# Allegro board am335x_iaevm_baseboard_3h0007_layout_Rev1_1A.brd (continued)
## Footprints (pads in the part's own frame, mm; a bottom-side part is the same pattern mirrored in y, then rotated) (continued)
HEADER_2X1
  rect 1.778x1.778 hole 1.016: 1(0,0)
  round 1.778 hole 1.016: 2(0,2.54)
HEADER_5X1
  rect 1.778x1.778 hole 1.016: 1(0,0)
  round 1.778 hole 1.016: 2(2.54,0) 3(5.08,0) 4(7.62,0) 5(10.16,0)
HEADER_10X2_TH
  oval 0.914x1.168 hole 0.66: 1(0,0) 2(0,1.27) 3(1.27,0) 4(1.27,1.27) 5(2.54,0) 6(2.54,1.27) 7(3.81,0) 8(3.81,1.27) 9(5.08,0) 10(5.08,1.27) 11(6.35,0) 12(6.35,1.27) 13(7.62,0) 14(7.62,1.27) 15(8.89,0) 16(8.89,1.27) 17(10.16,0) 18(10.16,1.27) 19(11.43,0) 20(11.43,1.27)
JUMP2X14-6040-1
  round 1.397 hole 1.016: 1(0,0) 2(0,2.54) 3(-2.54,0) 4(-2.54,2.54) 5(-5.08,0) 6(-5.08,2.54) 7(-7.62,0) 8(-7.62,2.54) 9(-10.16,0) 10(-10.16,2.54) 11(-12.7,0) 12(-12.7,2.54) 13(-15.24,0) 14(-15.24,2.54) 15(-17.78,0) 16(-17.78,2.54) 17(-20.32,0) 18(-20.32,2.54) 19(-22.86,0) 20(-22.86,2.54) 21(-25.4,0) 22(-25.4,2.54) 23(-27.94,0) 24(-27.94,2.54) 25(-30.48,0) 26(-30.48,2.54) 27(-33.02,0) 28(-33.02,2.54)
JUMP2X20-6040-1
  round 1.524 hole 1.016: 1(0,0) 2(0,2.54) 3(-2.54,0) 4(-2.54,2.54) 5(-5.08,0) 6(-5.08,2.54) 7(-7.62,0) 8(-7.62,2.54) 9(-10.16,0) 10(-10.16,2.54) 11(-12.7,0) 12(-12.7,2.54) 13(-15.24,0) 14(-15.24,2.54) 15(-17.78,0) 16(-17.78,2.54) 17(-20.32,0) 18(-20.32,2.54) 19(-22.86,0) 20(-22.86,2.54) 21(-25.4,0) 22(-25.4,2.54) 23(-27.94,0) 24(-27.94,2.54) 25(-30.48,0) 26(-30.48,2.54) 27(-33.02,0) 28(-33.02,2.54) 29(-35.56,0) 30(-35.56,2.54) 31(-38.1,0) 32(-38.1,2.54) 33(-40.64,0) 34(-40.64,2.54) 35(-43.18,0) 36(-43.18,2.54) 37(-45.72,0) 38(-45.72,2.54) 39(-48.26,0) 40(-48.26,2.54)
MC-306
  rect 1.3x1.9 smd: 1(-2.75,-1.6) 2(2.75,-1.6) 3(2.75,1.6) 4(-2.75,1.6)
MHC-W21-601-LF
  round 1.524 hole 1.092: (-11.5,-3.05)
  round 2.108 hole 1.6: (9.5,-3.05)
  rect 0.6x2 smd: 1(6.875,0) 2(4.375,0) 3(1.875,0) 4(-0.625,0) 5(-3.125,0) 6(-5.625,0) 7(-8.05,0) 8(-9.75,0) 9(9.375,0)
  rect 1x1.5 smd: 10(5.65,-17) 11(3.15,-17) 12(-4.35,-17) 13(-6.85,-17)
  rect 0.7x2 smd: 14(-12.25,0) 15(-11.05,0)
  rect 0.5x2 smd: 16(-7.27,0) 17(-6.475,0) 18(-4.775,0) 19(-1.475,0) 20(0.225,0) 21(1.025,0) 22(2.725,0) 23(3.525,0) 24(-8.9,0) 25(-3.975,0) 26(-2.275,0)
  rect 1.3x2.4 smd: 27(-14.15,-17.05) 28(14.15,-17.05)
MS920SE-FL27E
  rect 2.286x0.762 smd: 1(0,1) 2(0,-1)
NORCOMP_DB9M_TH
  rect 1.6x1.6 hole 1.092: 1(0.051,0)
  round 1.6 hole 1.092: 2(-2.718,0) 3(-5.486,0) 4(-8.255,0) 5(-11.024,0) 6(-1.346,2.845) 7(-4.102,2.845) 8(-6.871,2.845) 9(-9.639,2.845)
  round 5.08 hole 3.048: 10(-17.983,1.422) 11(7.01,1.422)
RAPC712
  round 4.064 hole 3.556: 1(0,0)
  round 3.683 hole 3.048: 2(-2.997,-4.801) 3(-6.248,0)
SKT-TSOP48SM
  rect 1.524x0.305 smd: 1(-9.716,5.753) 2(-9.716,5.253) 3(-9.716,4.752) 4(-9.716,4.252) 5(-9.716,3.754) 6(-9.716,3.254) 7(-9.716,2.753) 8(-9.716,2.253) 9(-9.716,1.753) 10(-9.716,1.252) 11(-9.716,0.754) 12(-9.716,0.254) 13(-9.716,-0.246) 14(-9.716,-0.747) 15(-9.716,-1.247) 16(-9.716,-1.748) 17(-9.716,-2.248) 18(-9.716,-2.746) 19(-9.716,-3.246) 20(-9.716,-3.747) 21(-9.716,-4.247) 22(-9.716,-4.747) 23(-9.716,-5.248) 24(-9.716,-5.748) 25(9.716,-5.753) 26(9.716,-5.253) 27(9.716,-4.752) 28(9.716,-4.252) 29(9.716,-3.754) 30(9.716,-3.254) 31(9.716,-2.753) 32(9.716,-2.253) 33(9.716,-1.753) 34(9.716,-1.252) 35(9.716,-0.754) 36(9.716,-0.254) 37(9.716,0.246) 38(9.716,0.747) 39(9.716,1.247) 40(9.716,1.748) 41(9.716,2.248) 42(9.716,2.746) 43(9.716,3.246) 44(9.716,3.747) 45(9.716,4.247) 46(9.716,4.747) 47(9.716,5.248) 48(9.716,5.748)
SM-7351-CAP-0402
  round 0.635 smd: 1(-0.508,0) 2(0.508,0)
SM-7351-CAP-0603
  rect 1.092x1.041 smd: 1(-0.85,0) 2(0.85,0)
SM-7351-CAP-0805
  rect 1.346x1.524 smd: 1(-1,0) 2(1,0)
SM-7351-CAP-2917
  rect 2.413x2.54 smd: 1(3.175,0) 2(-3.175,0)
SM-7351-CAP-SMDCAN
  rect 4.15x1.65 smd: 1(3.05,0) 2(-3.05,0)
SM-7351-IND-0805
  rect 1.397x1.549 smd: 1(-0.95,0) 2(0.95,0)
SM-7351-RES-0402
  round 0.635 smd: 1(-0.508,0) 2(0.508,0)
SM-7351-RES-0603
  rect 1.143x1.092 smd: 1(-0.9,0) 2(0.9,0)
SM-7351-RES-0805
  rect 1.143x1.549 smd: 1(-1.1,0) 2(1.1,0)
SM_CRY_SCC18
  rect 1.4x2.2 smd: 1(-1.25,3.2) 2(-1.25,-3.2) 3(1.25,-3.2) 4(1.25,3.2)
SM_LED_0805
  rect 1.15x1.194 smd: 1(1.125,0) 2(-1.125,0)
SM_RES_0805_KELV
  rect 1.4x1.65 smd: 1(-1.3,0) 2(1.3,0)
  rect 0.127x0.127 smd: 3(-0.377,-1.186) 4(0.377,-1.186)
SM_RES_LVK12
  rect 1.75x1.1 smd: 1(-1.375,0.7) 2(1.375,0.7) 3(-1.375,-0.7) 4(1.375,-0.7)
SMCJ15CA
  rect 2.4x3.3 smd: 1(-3.3,0) 2(3.3,0)
SMD_SLF7055T
  rect 1.5x2.2 smd: 1(-3.15,0) 2(3.15,0)
SMDFUSEBLK
  rect 4.242x3.81 smd: 1(-3.175,0) 2(3.175,0)
SMDMSOP_10
  rect 0.254x1.016 smd: 1(-1,-2.5) 2(-0.5,-2.5) 3(0,-2.5) 4(0.5,-2.5) 5(1,-2.5) 6(1,2.5) 7(0.5,2.5) 8(0,2.5) 9(-0.5,2.5) 10(-1,2.5)
SMDSC70-5
  rect 0.406x1.016 smd: 1(-0.65,-0.95) 2(0,-0.95) 3(0.65,-0.95) 4(0.65,0.95) 5(-0.65,0.95)
SOIC_8
  rect 0.61x2.184 smd: 1(-1.905,-2.603)
  oval 0.61x2.184 smd: 2(-0.635,-2.603) 3(0.635,-2.603) 4(1.905,-2.603) 5(1.905,2.603) 6(0.635,2.603) 7(-0.635,2.603) 8(-1.905,2.603)
SOT23-3
  rect 0.787x0.889 smd: D(0,1.003) G(-0.94,-1.003) S(0.94,-1.003)
SW_B3SL-1022P
  rect 2.75x1 smd: 1(2.875,-2) 2(-2.875,-2) 3(2.875,2) 4(-2.875,2)
TH_SW_T551101
  round 1.524 hole 1.092: 1(0,0) 2(0,-2.54) 3(0,-5.08) M1(-5.08,0) M2(-5.08,-5.08)
TH_TP_5002
  round 1.778 hole 1.016: 1(0,0)
TP_SMD1MMCIRCLE
  round 1.016 smd: 1(0,0)
U_5_DRL
  rect 0.3x0.45 smd: 1(-0.5,-0.675) 2(0,-0.675) 3(0.5,-0.675) 4(0.5,0.675) 5(-0.5,0.675)
U_6_DRY
  rect 0.305x0.508 smd: 1(-0.5,-0.439) 2(0,-0.439) 3(0.5,-0.439) 4(0.5,0.439) 5(0,0.439) 6(-0.5,0.439)
U_8_D
  rect 0.6x2 smd: 1(-1.905,-2.4) 2(-0.635,-2.4) 3(0.635,-2.4) 4(1.905,-2.4) 5(1.905,2.4) 6(0.635,2.4) 7(-0.635,2.4) 8(-1.905,2.4)
U_8_DCU
  rect 0.254x1.27 smd: 1(-0.749,-1.473) 2(-0.249,-1.473) 3(0.249,-1.473) 4(0.749,-1.473) 5(0.749,1.473) 6(0.249,1.473) 7(-0.249,1.473) 8(-0.749,1.473)
U_10_RSE
  rect 0.3x0.58 smd: 1(-0.75,-0.635) 2(-0.25,-0.635) 3(0.25,-0.635) 4(0.75,-0.635) 6(0.75,0.635) 7(0.25,0.635) 8(-0.25,0.635) 9(-0.75,0.635)
  rect 0.63x0.35 smd: 5(0.86,0) 10(-0.86,0)
U_16_D
  rect 0.6x2 smd: 1(-4.445,-2.4) 2(-3.175,-2.4) 3(-1.905,-2.4) 4(-0.635,-2.4) 5(0.635,-2.4) 6(1.905,-2.4) 7(3.175,-2.4) 8(4.445,-2.4) 9(4.445,2.4) 10(3.175,2.4) 11(1.905,2.4) 12(0.635,2.4) 13(-0.635,2.4) 14(-1.905,2.4) 15(-3.175,2.4) 16(-4.445,2.4)
U_20_DSBGA
  round 0.254 smd: A1(0.6,-0.8) A2(0.2,-0.8) A3(-0.2,-0.8) A4(-0.6,-0.8) B1(0.6,-0.4) B2(0.2,-0.4) B3(-0.2,-0.4) B4(-0.6,-0.4) C1(0.6,0) C2(0.2,0) C3(-0.2,0) C4(-0.6,0) D1(0.6,0.4) D2(0.2,0.4) D3(-0.2,0.4) D4(-0.6,0.4) E1(0.6,0.8) E2(0.2,0.8) E3(-0.2,0.8) E4(-0.6,0.8)
U_48_RSL
  rect 0.85x0.2 smd: 1(-2.975,2.2) 2(-2.975,1.8) 3(-2.975,1.4) 4(-2.975,1) 5(-2.975,0.6) 6(-2.975,0.2) 7(-2.975,-0.2) 8(-2.975,-0.6) 9(-2.975,-1) 10(-2.975,-1.4) 11(-2.975,-1.8) 12(-2.975,-2.2) 25(2.975,-2.2) 26(2.975,-1.8) 27(2.975,-1.4) 28(2.975,-1) 29(2.975,-0.6) 30(2.975,-0.2) 31(2.975,0.2) 32(2.975,0.6) 33(2.975,1) 34(2.975,1.4) 35(2.975,1.8) 36(2.975,2.2)
  rect 0.2x0.85 smd: 13(-2.2,-2.975) 14(-1.8,-2.975) 15(-1.4,-2.975) 16(-1,-2.975) 17(-0.6,-2.975) 18(-0.2,-2.975) 19(0.2,-2.975) 20(0.6,-2.975) 21(1,-2.975) 22(1.4,-2.975) 23(1.8,-2.975) 24(2.2,-2.975) 37(2.2,2.975) 38(1.8,2.975) 39(1.4,2.975) 40(1,2.975) 41(0.6,2.975) 42(0.2,2.975) 43(-0.2,2.975) 44(-0.6,2.975) 45(-1,2.975) 46(-1.4,2.975) 47(-1.8,2.975) 48(-2.2,2.975)
  rect 4.05x4.05 smd: PPAD(-0.225,0.225)
unnamed
  round 1.27 hole 6.35 unplated: (0,0)
USB_STD_A_TH
  round 1.676 hole 0.914: 1(0,0) 2(2.5,0) 3(4.5,0) 4(7,0)
  round 2.794 hole 2.311: S1(-3.073,-2.718) S2(10.058,-2.718)
VLCF5020T
  custom 0.525x0.525 smd: 1(-1.7,0) 2(1.7,0)
ZX62-AB-5PA
  rect 1.9x1.9 smd: (-1.2,-2.675) (1.2,-2.675)
  rect 0.4x1.35 smd: 1(-1.3,0) 2(-0.65,0) 3(0,0) 4(0.65,0) 5(1.3,0)
  rect 2.1x1.6 smd: S1(-3.1,-0.125) S2(3.1,-0.125)
  rect 1.8x1.9 smd: S3(-4.1,-2.675) S4(4.1,-2.675)

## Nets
DGND: BT1.2(NEG) C1.2 C16.2 C17.2 C19.2 C23.2 C24.2 C25.2 C27.2 C28.2 C29.2 C30.2 C31.2 C32.2 C34.2 C35.2 C36.2 C41.2 C42.2 C43.2 C45.2 C46.2 C47.2 C48.2 C50.2 C52.2 C53.2 C56.2 C60.2 C61.2 C62.2 C64.2 C65.2 C66.2 C68.2 C69.2 C70.2 C71.2 C72.2 C73.2 C76.2 C77.2 C78.2 C79.2 C80.2 C82.2 C83.2 C84.2(NEG) C85.2 C86.2 C88.2 C89.2 C90.2 C91.2 C92.2 C93.2 C94.2 C96.2 C97.2 C98.2 C101.2 C102.2 C103.2 C104.2 C107.2 C108.2 C109.2 C110.2 C111.2 C112.2 C113.2 C114.2 C115.2 C116.2 C117.2 C118.2 C125.2 C126.2 C127.2 C128.2 C129.2 C130.2 C131.2 C132.2 C133.2 C134.2 C135.2 C136.2 C137.2 C138.2 C139.2 C140.2 C141.2 C148.2 C155.2 C156.2 C174.2 C175.2 C177.2 C179.2 C180.2 C181.2 C182.2(NEG) C183.2 C184.2 C185.2(NEG) C186.2 C187.2 C188.2 C189.2 C195.2 C202.2 C215.2 C216.2 C217.2 C218.2 C219.2 C220.2 C221.2 C222.2 C232.2 C233.2 C234.2 C235.2 C236.2 C237.2 C238.2 C239.2 C240.2 C241.2 C245.2 C246.2 C247.2 C249.2 C250.2 C251.2 C252.2 C253.2 C254.2 C255.2 C257.2 C258.2 C259.2 C260.2 C261.2 C262.2 C263.2 C264.2 C265.2 C266.2 C267.2 C269.2 C270.2 C273.2 C274.2 D2.2(ANODE) D3.1(CATHODE) D9.2(ANODE) D10.2(ANODE) FB10.2 FB14.1 FB19.1 J1.2 J1.3 J2.8(GND#8) J2.10(GND#10) J2.12(GND#12) J2.16(GND#16) J2.20(GND#20) J3.27 J3.28 J4.7 J4.8 J5.1 J5.10 J5.11 J5.20 J5.30 J5.37 J6.3 J6.14 J6.20 J6.25 J7.19 J7.20 J8.19 J8.20 J9.10 J12.5 J12.10 J12.11 J13.3(#3_MMC+/MMCM/RSMMC/MMC/SD) J13.6(#6_MMC+/MMCM/RSMMC/MMC/SD) J13.18(#3_MINISD) J13.21(#6_MINISD) J13.27(GND1) J13.28(GND2) J14.5(GND) J17.3 J18.4(GND) J19.5 J19.10 J19.19 J19.20 Q1.S(SOURCE) Q2.S(SOURCE) Q3.S(SOURCE) Q4.S(SOURCE) R2.1(P1) R4.1(P1) R22.1(P1) R48.1(P1) R64.2(P2) R65.1(P1) R73.1(P1) R79.1(P1) R86.1(P1) R93.1(P1) R94.1(P1) R95.1(P1) R112.1(P1) R114.1(P1) R115.1(P1) R116.1(P1) R117.1(P1) R118.1(P1) R119.1(P1) R120.1(P1) R121.1(P1) R122.1(P1) R123.1(P1) R124.1(P1) R125.1(P1) R126.1(P1) R127.1(P1) R128.1(P1) R129.1(P1) R274.1(P1) R381.1(P1) R383.2(P2) R385.1(P1) R387.2(P2) R521.1(P1) R541.1(P1) SW1.M1 SW1.M2 SW2.1 SW2.2 TP27.1 TP28.1 TP29.1 TP30.1 U1.4(GND) U2.A1(VSS#A1) U2.A18(VSS#A18) U2.F8(VSS#F8) U2.G8(VSS#G8) U2.G9(VSS#G9) U2.G11(VSS#G11) U2.G12(VSS#G12) U2.H6(VSS#H6) U2.H7(VSS#H7) U2.H8(VSS#H8) U2.H9(VSS#H9) U2.H10(VSS#H10) U2.H12(VSS#H12) U2.J6(VSS#J6) U2.J7(VSS#J7) U2.J8(VSS#J8) U2.J9(VSS#J9) U2.J10(VSS#J10) U2.J11(VSS#J11) U2.K7(VSS#K7) U2.K9(VSS#K9) U2.K10(VSS#K10) U2.K11(VSS#K11) U2.L10(VSS#L10) U2.L11(VSS#L11) U2.L12(VSS#L12) U2.L13(VSS#L13) U2.M6(VSS#M6) U2.M7(VSS#M7) U2.M8(VSS#M8) U2.M9(VSS#M9) U2.M10(VSS#M10) U2.M12(VSS#M12) U2.M14(VSSA_USB#M14) U2.N7(VSS#N7) U2.N10(VSS#N10) U2.N11(VSS#N11) U2.N14(VSSA_USB#N14) U2.V1(VSS#V1) U2.V18(VSS#V18) U4.15(GNDIO) U4.17(REFGND) U4.34(GND1) U4.43(GND2) U4.PPAD(GNDP) U5.2(GND) U6.4(GND) U6.5(2A) U6.6(2B) U7.1(A0) U7.2(A1) U7.3(A2) U7.4(VSS) U8.A3(VSS#A3) U8.A7(VSSQ#A7) U8.B2(VSSQ#B2) U8.B8(VSSQ#B8) U8.D2(VSSQ#D2) U8.D8(VSSQ#D8) U8.E3(VSS#E3) U8.E7(VSSDL) U8.J1(VSS#J1) U8.K9(VSS#K9) U9.13(GND#13) U9.25(GND#25) U9.36(GND#36) U9.48(GND#48) U18.15(GND) U19.5(GND) U20.5(GND) U21.4(GND) U22.1(GND) U23.4(GND) U24.B4(SYNC) U24.C1(PGND#C1) U24.C2(PGND#C2) U24.C3(GND#C3) U24.D3(GND#D3) U24.E4(GND#E4) U27.1(A1) U27.2(A0) U27.7(GND) U29.1(GND) U30.4(GND) U31.A3(VSS#A3) U31.A7(VSSQ#A7) U31.B2(VSSQ#B2) U31.B8(VSSQ#B8) U31.D2(VSSQ#D2) U31.D8(VSSQ#D8) U31.E3(VSS#E3) U31.E7(VSSDL) U31.J1(VSS#J1) U31.K9(VSS#K9) U32.1(A1) U32.7(GND)
GND_OSC0: C4.2 C5.2 C67.2 U2.V11(VSS_OSC)
GND_OSC1: C2.1 C3.1 U2.A5(VSS_RTC)
GNDA_ADC: C63.2 FB10.1 R45.1(P1) U2.E8(VSSA_ADC)
GNDA_TSC: C11.2 C12.2 C13.2 C14.2 J9.11 J9.12 R45.2(P2) R51.2(P2)
GNDUSB0: FB14.2 J14.S1 J14.S2 J14.S3 J14.S4
GNDUSB1: FB19.2 J18.S1 J18.S2
V1_8D: C133.1 C138.1 C261.1 J3.1 J8.2 R472.1(P1)
V3_3D: C134.1 C135.1 C140.1 C175.1 C215.1 C222.1 C245.1 J5.39 J6.15 J9.2 R68.1(P1) R386.2(P2) R453.2(P2) R454.2(P2) R455.2(P2) R544.2(P2) U18.16(VCC) U27.6(VS) U32.6(VS)
V5_0D: C132.1 C136.1 C137.1 C184.1 C269.1 C270.1 J3.2 J7.1 J7.2 R520.2(P2) U22.2(IN#2) U22.3(IN#3) U24.E1(VOUT#E1) U24.E2(VOUT#E2) U29.2(IN#2) U29.3(IN#3)
V5_0D_EN: R386.1(P1) U24.A4(EN)
VBAT: C84.1(POS) C85.1 C86.1 C88.1 C112.1 C139.1 C141.1 C187.1 C234.1 C236.1 C238.1 C240.1 C250.1 C251.1 C252.1 C253.1 C254.1 C263.1 J6.19 J8.1 J19.1 J19.2 R50.2(P2) R80.2(P2) R81.2(P2) R82.2(P2) R83.2(P2) R239.2(P2) SW1.2 TP25.1 U4.3(VCC3) U4.6(VCC6) U4.13(VCCIO) U4.23(VCC5) U4.28(VCC7) U4.36(VCC1) U4.41(VCC2) U4.47(VCC4) U5.1(IN) U5.3(EN) U24.A1(VIN#A1) U24.A2(VIN#A2)
VBUS0_OTG_CAP: C182.1(POS) J36.2
VBUS1_OTG_CAP: C185.1(POS) J37.2 R558.2(P2)
VDD1_SMPS: J19.6 R46.1(I1) R469.1(P1) U32.8(VBUS)
VDD2_SMPS: J19.7 R32.1(I1) R468.1(P1) U27.8(VBUS)
VDD3_SMPS: C235.1 J19.8 R470.1(P1)
VDD_CORE: C16.1 C17.1 C19.1 C23.1 C24.1 C34.1 C35.1 C36.1 C232.1 R32.2(I2) U2.F6(VDD_CORE#F6) U2.F7(VDD_CORE#F7) U2.G6(VDD_CORE#G6) U2.G7(VDD_CORE#G7) U2.G10(VDD_CORE#G10) U2.H11(VDD_CORE#H11) U2.J12(VDD_CORE#J12) U2.K6(VDD_CORE#K6) U2.K8(VDD_CORE#K8) U2.K12(VDD_CORE#K12) U2.L6(VDD_CORE#L6) U2.L7(VDD_CORE#L7) U2.L8(VDD_CORE#L8) U2.L9(VDD_CORE#L9) U2.M11(VDD_CORE#M11) U2.M13(VDD_CORE#M13) U2.N8(VDD_CORE#N8) U2.N9(VDD_CORE#N9) U2.N12(VDD_CORE#N12) U2.N13(VDD_CORE#N13)
VDD_MPU: C41.1 C52.1 C53.1 C56.1 C83.1 C246.1 R46.2(I2) U2.F10(VDD_MPU#F10) U2.F11(VDD_MPU#F11) U2.F12(VDD_MPU#F12) U2.F13(VDD_MPU#F13) U2.G13(VDD_MPU#G13) U2.H13(VDD_MPU#H13) U2.J13(VDD_MPU#J13)
VDD_RTC: C65.1 U2.D6(CAP_VDD_RTC)
VDDA1P8V_USB0: C61.1 R502.2(I2) U2.N16(VDDA1P8V_USB0) U2.R16(VDDA1P8V_USB1)
VDDA3P3V_USB0: C62.1 R504.2(I2) U2.N15(VDDA3P3V_USB0) U2.R15(VDDA3P3V_USB1)
VDDA_ADC: FB9.1 Q5.S(SOURCE) R30.1(P1) R501.2(I2) R565.2(P2)
VDDMPU_MON: R561.1(P1) U2.A2(VDD_MPU_MON)
VDDS_DDR: C125.1 C126.1 C155.1 C156.1 C174.1 C181.1 C188.1 C189.1 C195.1 C202.1 C216.1 C217.1 C218.1 C219.1 C220.1 C221.1 C266.1 C267.1 J19.9 R467.1(P1) R508.1(I1) R542.1(P1) U8.A1(VDD#A1) U8.A9(VDDQ#A9) U8.C1(VDDQ#C1) U8.C3(VDDQ#C3) U8.C7(VDDQ#C7) U8.C9(VDDQ#C9) U8.E1(VDDL) U8.E9(VDD#E9) U8.H9(VDD#H9) U8.L1(VDD#L1) U31.A1(VDD#A1) U31.A9(VDDQ#A9) U31.C1(VDDQ#C1) U31.C3(VDDQ#C3) U31.C7(VDDQ#C7) U31.C9(VDDQ#C9) U31.E1(VDDL) U31.E9(VDD#E9) U31.H9(VDD#H9) U31.L1(VDD#L1)
VDDS_OSC: C67.1 R506.1(I1) U2.R11(VDDS_OSC)
VDDS_PLL_CORE_LCD: C64.1 R503.1(I1) U2.R10(VDDS_PLL_CORE_LCD)
VDDS_PLL_DDR: C73.1 R507.2(I2) U2.E7(VDDS_PLL_DDR)
VDDS_PLL_MPU: C70.1 R497.2(I2) U2.H15(VDDS_PLL_MPU)
VDDS_RTC: C66.1 R505.1(I1) U2.D7(VDDS_RTC)
VDDS_SRAM_CORE_BG: C68.1 R500.2(I2) U2.E9(VDDS_SRAM_CORE_BG)
VDDS_SRAM_MPU_BB: C69.1 R499.2(I2) U2.D10(VDDS_SRAM_MPU_BB)
VDDSHV1: C127.1 C128.1 C129.1 C130.1 C131.1 FB1.1 FB2.1 R130.2(P2) R131.2(P2) R132.2(P2) R493.2(I2) U9.12(VCC#12) U9.34(VCC#34) U9.37(VCC#37) U9.39(VCC#39)
VDDSHV2: C148.1 FB5.1 J6.11 R545.2(I2)
VDDSHV3: FB20.1 FB21.1 R546.2(I2)
VDDSHV4: C180.1 C255.1 FB4.1 J13.4(#4_MMC+/MMCM/RSMMC/MMC/SD) J13.19(#4_MINISD) R365.2(P2) R366.2(P2) R367.2(P2) R368.2(P2) R369.2(P2) R370.2(P2) R371.2(P2) R372.2(P2) R373.2(P2) R494.2(I2) U19.10(VCC) U20.10(VCC)
VDDSHV5: FB3.1 FB6.1 R495.2(I2)
VDDSHV6: C115.1 C116.1 FB7.1 FB8.1 J2.5(TVDD) R6.2(P2) R70.2(P2) R71.2(P2) R72.2(P2) R96.2(P2) R97.2(P2) R98.2(P2) R99.2(P2) R100.2(P2) R101.2(P2) R102.2(P2) R103.2(P2) R104.2(P2) R105.2(P2) R106.2(P2) R107.2(P2) R108.2(P2) R109.2(P2) R110.2(P2) R111.2(P2) R378.2(P2) R382.1(P1) R412.1(P1) R496.2(I2) R547.2(P2) R548.2(P2) R552.2(P2) R553.2(P2) R554.2(P2) R555.2(P2) R559.2(P2) U7.8(VCC) U21.1(VCC)
AM335X_AIN0: J9.14 U2.B6(AIN0)
AM335X_AIN1: J9.16 U2.C7(AIN1)
AM335X_AIN2: J9.18 U2.B7(AIN2)
AM335X_AIN3: J9.20 U2.A7(AIN3)
AM335X_AIN4: J9.13 U2.C8(AIN4)
AM335X_AIN5: J9.15 U2.B8(AIN5)
AM335X_AIN6: J9.17 U2.A8(AIN6)
AM335X_AIN7: J9.19 R23.1(P1) R571.2(P2) U2.C9(AIN7)
AM335X_DDR_A0: R18.1(P1) U2.F3(DDR_A0)
AM335X_DDR_A1: R21.1(P1) U2.H1(DDR_A1)
AM335X_DDR_A2: R31.1(P1) U2.E4(DDR_A2)
AM335X_DDR_A3: R33.1(P1) U2.C3(DDR_A3)
AM335X_DDR_A4: R34.1(P1) U2.C2(DDR_A4)
AM335X_DDR_A5: R35.1(P1) U2.B1(DDR_A5)
AM335X_DDR_A6: R36.1(P1) U2.D5(DDR_A6)
AM335X_DDR_A7: R37.1(P1) U2.E2(DDR_A7)
AM335X_DDR_A8: R38.1(P1) U2.D4(DDR_A8)
AM335X_DDR_A9: R39.1(P1) U2.C1(DDR_A9)
AM335X_DDR_A10: R40.1(P1) U2.F4(DDR_A10)
AM335X_DDR_A11: R41.1(P1) U2.F2(DDR_A11)
AM335X_DDR_A12: R42.1(P1) U2.E3(DDR_A12)
AM335X_DDR_A13: R43.1(P1) U2.H3(DDR_A13)
AM335X_DDR_A14: R44.1(P1) U2.H4(DDR_A14)
AM335X_DDR_BA0: R47.1(P1) U2.C4(DDR_BA0)
AM335X_DDR_BA1: R49.1(P1) U2.E1(DDR_BA1)
AM335X_DDR_BA2: R549.1(P1) U2.B3(DDR_BA2)
AM335X_DDR_CASN: R13.1(P1) U2.F1(DDR_CASN)
AM335X_DDR_CKE: R537.1(P1) U2.G3(DDR_CKE)
AM335X_DDR_CLK: R11.1(P1) U2.D2(DDR_CK)
AM335X_DDR_CLKN: R12.1(P1) U2.D1(DDR_CKN)
AM335X_DDR_CSN: R538.1(P1) U2.H2(DDR_CSN0)
AM335X_DDR_D0: R429.1(P1) U2.M3(DDR_D0)
AM335X_DDR_D1: R522.1(P1) U2.M4(DDR_D1)
AM335X_DDR_D2: R523.1(P1) U2.N1(DDR_D2)
AM335X_DDR_D3: R524.1(P1) U2.N2(DDR_D3)
AM335X_DDR_D4: R525.1(P1) U2.N3(DDR_D4)
AM335X_DDR_D5: R526.1(P1) U2.N4(DDR_D5)
AM335X_DDR_D6: R527.1(P1) U2.P3(DDR_D6)
AM335X_DDR_D7: R528.1(P1) U2.P4(DDR_D7)
AM335X_DDR_D8: R529.1(P1) U2.J1(DDR_D8)
AM335X_DDR_D9: R530.1(P1) U2.K1(DDR_D9)
AM335X_DDR_D10: R531.1(P1) U2.K2(DDR_D10)
AM335X_DDR_D11: R532.1(P1) U2.K3(DDR_D11)
AM335X_DDR_D12: R533.1(P1) U2.K4(DDR_D12)
AM335X_DDR_D13: R534.1(P1) U2.L3(DDR_D13)
AM335X_DDR_D14: R535.1(P1) U2.L4(DDR_D14)
AM335X_DDR_D15: R536.1(P1) U2.M1(DDR_D15)
AM335X_DDR_DQM0: R16.1(P1) U2.M2(DDR_DQM0)
AM335X_DDR_DQM1: R19.1(P1) U2.J2(DDR_DQM1)
AM335X_DDR_DQS0: R17.1(P1) U2.P1(DDR_DQS0)
AM335X_DDR_DQS1: R20.1(P1) U2.L1(DDR_DQS1)
AM335X_DDR_DQSN0: R539.1(P1) U2.P2(DDR_DQSN0)
AM335X_DDR_DQSN1: R540.1(P1) U2.L2(DDR_DQSN1)
AM335X_DDR_RASN: R14.1(P1) U2.G4(DDR_RASN)
AM335X_DDR_WEN: R15.1(P1) U2.B2(DDR_WEN)
AM335X_DDRODT: R543.1(P1) U2.G1(DDR_ODT)
AM335X_ECAP0_IN_PWM0_OUT: R210.1(P1) R255.2(P2) U2.C18(ECAP0_IN_PWM0_OUT)
AM335X_EXT_WAKEUP: R207.2(P2) U2.C5(EXT_WAKEUP)
AM335X_EXTINTN: R113.1(P1) U2.B18(NMIN)
AM335X_GPMC_A0: R193.2(P2) U2.R13(GPMC_A0)
AM335X_GPMC_A1: R574.2(P2) U2.V14(GPMC_A1)
AM335X_GPMC_A2: R575.2(P2) U2.U14(GPMC_A2)
AM335X_GPMC_A3: R576.2(P2) U2.T14(GPMC_A3)
AM335X_GPMC_A4: R206.2(P2) U2.R14(GPMC_A4)
AM335X_GPMC_A5: R209.2(P2) R509.2(P2) U2.V15(GPMC_A5)
AM335X_GPMC_A6: R214.2(P2) U2.U15(GPMC_A6)
AM335X_GPMC_A7: R217.2(P2) R510.2(P2) U2.T15(GPMC_A7)
AM335X_GPMC_A8: R223.2(P2) R511.2(P2) U2.V16(GPMC_A8)
AM335X_GPMC_A9: R226.2(P2) R512.2(P2) U2.U16(GPMC_A9)
AM335X_GPMC_A10: R230.2(P2) R384.1(P1) U2.T16(GPMC_A10)
AM335X_GPMC_A11: R233.2(P2) U2.V17(GPMC_A11)
AM335X_GPMC_AD0: R140.2(P2) R171.1(P1) U2.U7(GPMC_AD0)
AM335X_GPMC_AD1: R141.2(P2) R169.1(P1) U2.V7(GPMC_AD1)
AM335X_GPMC_AD2: R142.2(P2) R167.1(P1) U2.R8(GPMC_AD2)
AM335X_GPMC_AD3: R143.2(P2) R165.1(P1) U2.T8(GPMC_AD3)
AM335X_GPMC_AD4: R144.2(P2) R163.1(P1) U2.U8(GPMC_AD4)
AM335X_GPMC_AD5: R145.2(P2) R161.1(P1) U2.V8(GPMC_AD5)
AM335X_GPMC_AD6: R146.2(P2) R159.1(P1) U2.R9(GPMC_AD6)
AM335X_GPMC_AD7: R147.2(P2) R157.1(P1) U2.T9(GPMC_AD7)
AM335X_GPMC_AD8: R148.2(P2) R261.2(P2) U2.U10(GPMC_AD8)
AM335X_GPMC_AD9: R149.2(P2) R263.2(P2) U2.T10(GPMC_AD9)
AM335X_GPMC_AD10: R150.2(P2) R242.2(P2) U2.T11(GPMC_AD10)
AM335X_GPMC_AD11: R151.2(P2) R243.2(P2) U2.U12(GPMC_AD11)
AM335X_GPMC_AD12: R152.2(P2) R264.2(P2) U2.T12(GPMC_AD12)
AM335X_GPMC_AD13: R153.2(P2) R247.2(P2) U2.R12(GPMC_AD13)
AM335X_GPMC_AD14: R154.2(P2) R248.2(P2) U2.V13(GPMC_AD14)
AM335X_GPMC_AD15: R155.2(P2) R253.2(P2) U2.U13(GPMC_AD15)
AM335X_GPMC_ADVN_ALE: R137.2(P2) R182.2(P2) U2.R7(GPMC_ADVN_ALE)
AM335X_GPMC_BE0N_CLE: R136.2(P2) R184.2(P2) U2.T6(GPMC_BEN0_CLE)
AM335X_GPMC_BE1N: R577.2(P2) U2.U18(GPMC_BEN1)
AM335X_GPMC_CLK: R572.2(P2) U2.V12(GPMC_CLK)
AM335X_GPMC_CS0N: R135.2(P2) R183.2(P2) U2.V6(GPMC_CSN0)
AM335X_GPMC_CS1N: R175.1(P1) U2.U9(GPMC_CSN1)
AM335X_GPMC_CS2N: R173.1(P1) U2.V9(GPMC_CSN2)
AM335X_GPMC_CS3N: R573.2(P2) U2.T13(GPMC_CSN3)
AM335X_GPMC_OEN_REN: R134.2(P2) R189.2(P2) U2.T7(GPMC_OEN_REN)
AM335X_GPMC_WAIT: R133.2(P2) R179.2(P2) U2.T17(GPMC_WAIT0)
AM335X_GPMC_WEN: R138.2(P2) R191.2(P2) U2.U6(GPMC_WEN)
AM335X_GPMC_WPN: R139.2(P2) R180.2(P2) U2.U17(GPMC_WPN)
AM335X_I2C0_SCL: R58.2(P2) R265.2(P2) R547.1(P1) R551.2(P2) U2.C16(I2C0_SCL) U7.6(SCL)
AM335X_I2C0_SDA: R59.2(P2) R268.2(P2) R548.1(P1) R550.2(P2) U2.C17(I2C0_SDA) U7.5(SDA)
AM335X_LCD_AC_BIAS_EN: R273.2(P2) U2.R6(LCD_AC_BIAS_EN)
AM335X_LCD_DATA0: R96.1(P1) R240.2(P2) SW3.16 U2.R1(LCD_DATA0)
AM335X_LCD_DATA1: R97.1(P1) R241.2(P2) SW3.15 U2.R2(LCD_DATA1)
AM335X_LCD_DATA2: R98.1(P1) R245.2(P2) SW3.14 U2.R3(LCD_DATA2)
AM335X_LCD_DATA3: R99.1(P1) R246.2(P2) SW3.13 U2.R4(LCD_DATA3)
AM335X_LCD_DATA4: R100.1(P1) R251.2(P2) SW3.12 U2.T1(LCD_DATA4)
AM335X_LCD_DATA5: R101.1(P1) R252.2(P2) SW3.11 U2.T2(LCD_DATA5)
AM335X_LCD_DATA6: R102.1(P1) R270.2(P2) SW3.10 U2.T3(LCD_DATA6)
AM335X_LCD_DATA7: R103.1(P1) R259.2(P2) SW3.9 U2.T4(LCD_DATA7)
AM335X_LCD_DATA8: R104.1(P1) R262.2(P2) SW4.16 U2.U1(LCD_DATA8)
AM335X_LCD_DATA9: R105.1(P1) R266.2(P2) SW4.15 U2.U2(LCD_DATA9)
AM335X_LCD_DATA10: R106.1(P1) R256.2(P2) SW4.14 U2.U3(LCD_DATA10)
AM335X_LCD_DATA11: R107.1(P1) R267.2(P2) SW4.13 U2.U4(LCD_DATA11)
AM335X_LCD_DATA12: R108.1(P1) R257.2(P2) SW4.12 U2.V2(CD_DATA12)
AM335X_LCD_DATA13: R109.1(P1) R258.2(P2) SW4.11 U2.V3(LCD_DATA13)
AM335X_LCD_DATA14: R110.1(P1) R260.2(P2) SW4.10 U2.V4(LCD_DATA14)
AM335X_LCD_DATA15: R111.1(P1) R254.2(P2) SW4.9 U2.T5(LCD_DATA15)
AM335X_LCD_HSYNC: R272.2(P2) U2.R5(LCD_HSYNC)
AM335X_LCD_PCLK: R269.2(P2) U2.V5(LCD_PCLK)
AM335X_LCD_VSYNC: R271.2(P2) U2.U5(LCD_VSYNC)
AM335X_MCASP0_ACLKR: R88.2(P2) R218.2(P2) R379.2(P2) U2.B12(MCASP0_ACLKR)
AM335X_MCASP0_ACLKX: R194.2 U2.A13(MCASP0_ACLKX)
AM335X_MCASP0_AHCLKR: R85.2(P2) R211.1(P1) U2.C12(MCASP0_AHCLKR)
AM335X_MCASP0_AHCLKX: R92.2(P2) R234.2(P2) U2.A14(MCASP0_AHCLKX)
AM335X_MCASP0_AXR0: R203.1(P1) U2.D12(MCASP0_AXR0)
AM335X_MCASP0_AXR1: R227.2(P2) U2.D13(MCASP0_AXR1)
AM335X_MCASP0_FSR: R90.2(P2) R224.2(P2) U2.C13(MCASP0_FSR)
AM335X_MCASP0_FSX: R199.1(P1) U2.B13(MCASP0_FSX)
AM335X_MII1_COL: R66.2(P2) R231.2(P2) U2.H16(MII1_COL)
AM335X_MII1_CRS: R235.2(P2) U2.H17(MII1_CRS)
AM335X_MII1_MDIO_CLK: R195.1(P1) U2.M18(MDIO_CLK)
AM335X_MII1_MDIO_DATA: R192.1(P1) U2.M17(MDIO_DATA)
AM335X_MII1_REFCLK: R188.1(P1) R410.1(P1) U2.H18(MII1_REFCLK)
AM335X_MII1_RXCLK: R162.2(P2) U2.L18(MII1_RXCLK)
AM335X_MII1_RXD0: R190.1(P1) U2.M16(MII1_RXD0)
AM335X_MII1_RXD1: R185.2(P2) U2.L15(MII1_RXD1)
AM335X_MII1_RXD2: R164.2(P2) U2.L16(MII1_RXD2)
AM335X_MII1_RXD3: R158.2(P2) U2.L17(MII1_RXD3)
AM335X_MII1_RXDV: R168.2(P2) U2.J17(MII1_RXDV)
AM335X_MII1_RXERR: R237.2(P2) U2.J15(MII1_RXERR)
AM335X_MII1_TXCLK: R160.2(P2) U2.K18(MII1_TXCLK)
AM335X_MII1_TXD0: R174.2(P2) U2.K17(MII1_TXD0)
AM335X_MII1_TXD1: R172.2(P2) U2.K16(MII1_TXD1)
AM335X_MII1_TXD2: R166.2(P2) U2.K15(MII1_TXD2)
AM335X_MII1_TXD3: R170.2(P2) U2.J18(MII1_TXD3)
AM335X_MII1_TXEN: R238.2(P2) U2.J16(MII1_TXEN)
AM335X_MMC_CLK: R197.2(P2) R398.2(P2) U2.G17(MMC0_CLK)
AM335X_MMC_CMD: R200.2(P2) R397.2(P2) U2.G18(MMC0_CMD)
AM335X_MMC_D0: R204.2(P2) R399.2(P2) U2.G16(MMC0_DAT0)
AM335X_MMC_D1: R212.2(P2) R400.2(P2) U2.G15(MMC0_DAT1)
AM335X_MMC_D2: R215.2(P2) R401.2(P2) U2.F18(MMC0_DAT2)
AM335X_MMC_D3: R219.2(P2) R396.2(P2) U2.F17(MMC0_DAT3)
AM335X_OSC0_IN: C4.1 R7.2(P2) U2.V10(XTALIN) Y2.3
AM335X_OSC0_OUT: R8.1(P1) U2.U11(XTALOUT)
AM335X_OSC1_IN: C2.2 U2.A6(RTC_XTALIN) Y1.4
AM335X_OSC1_OUT: R5.1(P1) U2.A4(RTC_XTALOUT)
AM335X_PORZ: R9.2(P2) U2.B15(PWRONRSTN)
AM335X_RTC_PORZ: R4.2(P2) U1.2(2B) U1.3(2Y) U2.B5(RTC_PWRONRSTN)
AM335X_SPI0_CS0: R55.2(P2) R176.2(P2) R552.1(P1) U2.A16(SPI0_CS0)
AM335X_SPI0_CS1: R78.2(P2) R208.1(P1) R380.2(P2) U2.C15(SPI0_CS1)
AM335X_SPI0_D0: R205.1(P1) U2.B17(SPI0_D0)
AM335X_SPI0_D1: R56.2(P2) R177.1(P1) R553.1(P1) U2.B16(SPI0_D1)
AM335X_SPI0_SCLK: R201.1(P1) U2.A17(SPI0_SCLK)
AM335X_UART0_CTSN: R61.2(P2) R213.1(P1) R364.2(P2) U2.E18(UART0_CTSN)
AM335X_UART0_RTSN: R62.2(P2) R216.1(P1) R362.2(P2) U2.E17(UART0_RTSN)
AM335X_UART0_RXD: R220.1(P1) R249.2(P2) R363.2(P2) U2.E15(UART0_RXD)
AM335X_UART0_TXD: R222.1(P1) R244.2(P2) R361.2(P2) U2.E16(UART0_TXD)
AM335X_UART1_CTSN: R84.2(P2) R225.1(P1) R555.1(P1) U2.D18(UART1_CTSN)
AM335X_UART1_RTSN: R87.2(P2) R229.1(P1) R554.1(P1) U2.D17(UART1_RTSN)
AM335X_UART1_RXD: R89.2(P2) R232.1(P1) U2.D16(UART1_RXD)
AM335X_UART1_TXD: R91.2(P2) R236.1(P1) U2.D15(UART1_TXD)
AM335X_USB0_CE: TP23.1 U2.M15(USB0_CE)
AM335X_USB0_DRVVBUS: R383.1(P1) U2.F16(USB0_DRVVBUS) U22.4(EN)
AM335X_USB0_VBUS: D9.1(CATHODE) R563.2 U2.P15(USB0_VBUS)
AM335X_USB1_CE: TP36.1 U2.P18(USB1_CE)
AM335X_USB1_DRVVBUS: R387.1(P1) U2.F15(USB1_DRVVBUS) U29.4(EN)
AM335X_USB1_VBUS: D10.1(CATHODE) R564.2 U2.T18(USB1_VBUS)
AM335X_VDDA_ADC: C63.1 R501.1(I1) U2.D8(VDDA_ADC)
AM335X_VDDS: C48.1 C50.1 C89.1 C96.1 C249.1 R498.1(I1) U2.E6(VDDS#E6) U2.E14(VDDS#E14) U2.F9(VDDS#F9) U2.K13(VDDS#K13) U2.N6(VDDS#N6) U2.P9(VDDS#P9) U2.P14(VDDS#P14)
AM335X_VDDS_DDR: C76.1 C77.1 C78.1 C79.1 C80.1 C82.1 C233.1 R508.2(I2) U2.E5(VDDS_DDR#E5) U2.F5(VDDS_DDR#F5) U2.G5(VDDS_DDR#G5) U2.H5(VDDS_DDR#H5) U2.J5(VDDS_DDR#J5) U2.K5(VDDS_DDR#K5) U2.L5(VDDS_DDR#L5)
AM335X_VDDSHV1: C31.1 C32.1 C258.1 R493.1(I1) U2.P7(VDDSHV1#P7) U2.P8(VDDSHV1#P8)
AM335X_VDDSHV2: C90.1 C92.1 C259.1 R545.1(I1) U2.P10(VDDSHV2#P10) U2.P11(VDDSHV2#P11)
AM335X_VDDSHV3: C93.1 C94.1 C273.1 R546.1(I1) U2.P12(VDDSHV3#P12) U2.P13(VDDSHV3#P13)
AM335X_VDDSHV4: C42.1 C43.1 C274.1 R494.1(I1) U2.H14(VDDSHV4#H14) U2.J14(VDDSHV4#J14)
AM335X_VDDSHV5: C45.1 C46.1 C257.1 R495.1(I1) U2.K14(VDDSHV5#K14) U2.L14(VDDSHV5#L14)
AM335X_VDDSHV6: C25.1 C27.1 C28.1 C29.1 C30.1 C47.1 C247.1 R496.1(I1) U2.E10(VDDSHV6#E10) U2.E11(VDDSHV6#E11) U2.E12(VDDSHV6#E12) U2.E13(VDDSHV6#E13) U2.F14(VDDSHV6#F14) U2.G14(VDDSHV6#G14) U2.N5(VDDSHV6#N5) U2.P5(VDDSHV6#P5) U2.P6(VDDSHV6#P6)
AM335X_XDMA_EVENT_INTR0: R76.2(P2) R221.2(P2) U2.A15(XDMA_EVENT_INTR0)
AM335X_XDMA_EVENT_INTR1: R77.2(P2) R228.2(P2) R250.2(P2) U2.D14(XDMA_EVENT_INTR1)
CAP_VBB_MPU: C72.1 U2.C10(CAP_VBB_MPU)
CAP_VDD_SRAM_CORE: C60.1 U2.D9(CAP_VDD_SRAM_CORE)
CAP_VDD_SRAM_MPU: C71.1 U2.D11(CAP_VDD_SRAM_MPU)
DDR_A0: R18.2(P2) U8.H8(A0) U31.H8(A0)
DDR_A1: R21.2(P2) U8.H3(A1) U31.H3(A1)
DDR_A2: R31.2(P2) U8.H7(A2) U31.H7(A2)
DDR_A3: R33.2(P2) U8.J2(A3) U31.J2(A3)
DDR_A4: R34.2(P2) U8.J8(A4) U31.J8(A4)
DDR_A5: R35.2(P2) U8.J3(A5) U31.J3(A5)
DDR_A6: R36.2(P2) U8.J7(A6) U31.J7(A6)
DDR_A7: R37.2(P2) U8.K2(A7) U31.K2(A7)
DDR_A8: R38.2(P2) U8.K8(A8) U31.K8(A8)
DDR_A9: R39.2(P2) U8.K3(A9) U31.K3(A9)
DDR_A10: R40.2(P2) U8.H2(A10) U31.H2(A10)
DDR_A11: R41.2(P2) U8.K7(A11) U31.K7(A11)
DDR_A12: R42.2(P2) U8.L2(A12) U31.L2(A12)
DDR_A13: R43.2(P2) U8.L8(A13) U31.L8(A13)
DDR_A14: R44.2(P2) U8.L3(A14) U31.L3(A14)
DDR_BA0: R47.2(P2) U8.G2(BA0) U31.G2(BA0)
DDR_BA1: R49.2(P2) U8.G3(BA1) U31.G3(BA1)
DDR_BA2: R549.2(P2) U8.G1(BA2) U31.G1(BA2)
DDR_CASN: R13.2(P2) U8.G7(CASN) U31.G7(CASN)
DDR_CKE: R537.2(P2) U8.F2(CKE) U31.F2(CKE)
DDR_CLK: R11.2(P2) U8.E8(CK) U31.E8(CK)
DDR_CLKN: R12.2(P2) U8.F8(CKN) U31.F8(CKN)
DDR_CSN: R538.2(P2) U8.G8(CSN) U31.G8(CSN)
DDR_D0: R429.2(P2) U8.C8(DQ0)
DDR_D1: R522.2(P2) U8.C2(DQ1)
DDR_D2: R523.2(P2) U8.D7(DQ2)
DDR_D3: R524.2(P2) U8.D3(DQ3)
DDR_D4: R525.2(P2) U8.D1(DQ4)
DDR_D5: R526.2(P2) U8.D9(DQ5)
DDR_D6: R527.2(P2) U8.B1(DQ6)
DDR_D7: R528.2(P2) U8.B9(DQ7)
DDR_D8: R529.2(P2) U31.C8(DQ0)
DDR_D9: R530.2(P2) U31.C2(DQ1)
DDR_D10: R531.2(P2) U31.D7(DQ2)
DDR_D11: R532.2(P2) U31.D3(DQ3)
DDR_D12: R533.2(P2) U31.D1(DQ4)
DDR_D13: R534.2(P2) U31.D9(DQ5)
DDR_D14: R535.2(P2) U31.B1(DQ6)
DDR_D15: R536.2(P2) U31.B9(DQ7)
DDR_DQM0: R16.2(P2) U8.B3(DM)
DDR_DQM1: R19.2(P2) U31.B3(DM)
DDR_DQS0: R17.2(P2) U8.B7(DQS)
DDR_DQS1: R20.2(P2) U31.B7(DQS)
DDR_DQSN0: R539.2(P2) U8.A8(DQSN)
DDR_DQSN1: R540.2(P2) U31.A8(DQSN)
DDR_ODT: R543.2(P2) U8.F9(ODT) U31.F9(ODT)
DDR_RASN: R14.2(P2) U8.F7(RASN) U31.F7(RASN)
DDR_VREF: R541.2(P2) R542.2(P2) U2.J4(DDR_VREF) U8.E2(VREF) U31.E2(VREF)
DDR_WEN: R15.2(P2) U8.F3(WEN) U31.F3(WEN)
EMU2: J2.17(EMU2) R76.1(P1)
EMU3: J2.18(EMU3) R77.1(P1)
EMU4: J2.19(EMU4) R78.1(P1)
EMU_RSTN: C260.1 J2.15(SRST) R517.1(P1)
ENZ_KALDO_1P8V: R48.2(P2) U2.B4(RTC_KALDO_ENN)
EXP0_P25: J3.25 R178.2(P2)
EXP3_P9: J6.9 TP35.1
EXP_ECAP0_IN_PWM0_OUT: J5.19 R210.2(P2)
EXP_GPMC_ADVN_ALE: J4.26 R182.1(P1)
EXP_GPMC_BE0N_CLE: J4.28 R184.1(P1)
EXP_GPMC_BE1N: J5.2 R186.1(P1)
EXP_GPMC_CLK: J4.23 R181.1(P1)
EXP_GPMC_CS0N: J4.25 R183.1(P1)
EXP_GPMC_CS3N: J5.4 R187.1(P1)
EXP_GPMC_OEN_REN: J5.6 R189.1(P1)
EXP_GPMC_WAIT: J4.19 R179.1(P1)
EXP_GPMC_WEN: J5.8 R191.1(P1)
EXP_GPMC_WPN: J4.21 R180.1(P1)
EXP_I2C1_SCL: J3.24 R176.1(P1)
EXP_I2C1_SDA: J3.23 R177.2(P2)
EXP_MII1_COL: J5.34 R231.1(P1)
EXP_MII1_CRS: J5.36 R235.1(P1)
EXP_MII1_MDIO_CLK: J5.9 R195.2(P2)
EXP_MII1_MDIO_DATA: J5.7 R192.2(P2)
EXP_MII1_REFCLK: J5.3 R188.2(P2)
EXP_MII1_RXCLK: J3.8 R162.1(P1)
EXP_MII1_RXD0: J5.5 R190.2(P2)
EXP_MII1_RXD1: J3.22 R185.1(P1)
EXP_MII1_RXD2: J3.10 R164.1(P1)
EXP_MII1_RXD3: J3.4 R158.1(P1)
EXP_MII1_RXDV: J3.14 R168.1(P1)
EXP_MII1_RXERR: J5.38 R237.1(P1)
EXP_MII1_TXCLK: J3.6 R160.1(P1)
EXP_MII1_TXD0: J3.20 R174.1(P1)
EXP_MII1_TXD1: J3.18 R172.1(P1)
EXP_MII1_TXD2: J3.12 R166.1(P1)
EXP_MII1_TXD3: J3.16 R170.1(P1)
EXP_MII1_TXEN: J5.40 R238.1(P1)
EXP_MMC0_CLK: J5.12 R197.1(P1)
EXP_MMC0_CMD: J5.14 R200.1(P1)
EXP_MMC0_DAT0: J5.16 R204.1(P1)
EXP_MMC0_DAT1: J5.22 R212.1(P1)
EXP_MMC0_DAT2: J5.24 R215.1(P1)
EXP_MMC0_DAT3: J5.26 R219.1(P1)
EXP_MMC1_CLK: J3.21 R175.2(P2)
EXP_MMC1_CMD: J3.19 R173.2(P2)
EXP_MMC1_DAT0: J3.17 R171.2(P2)
EXP_MMC1_DAT1: J3.15 R169.2(P2)
EXP_MMC1_DAT2: J3.13 R167.2(P2)
EXP_MMC1_DAT3: J3.11 R165.2(P2)
EXP_MMC1_DAT4: J3.9 R163.2(P2)
EXP_MMC1_DAT5: J3.7 R161.2(P2)
EXP_MMC1_DAT6: J3.5 R159.2(P2)
EXP_MMC1_DAT7: J3.3 R157.2(P2)
EXP_PB_POWERON: J4.12 R63.2(P2)
EXP_SPI0_CLK: J5.13 R201.2(P2)
EXP_SPI0_CS1: J5.17 R208.2(P2)
EXP_SPI0_D0: J5.15 R205.2(P2)
EXP_UART0_CTSN: J5.21 R213.2(P2)
EXP_UART0_RTSN: J5.23 R216.2(P2)
EXP_UART0_RXD: J5.25 R220.2(P2)
EXP_UART0_TXD: J5.27 R222.2(P2)
EXP_UART1_CTSN: J5.29 R225.2(P2)
EXP_UART1_RTSN: J5.31 R229.2(P2)
EXP_UART1_RXD: J5.33 R232.2(P2)
EXP_UART1_TXD: J5.35 R236.2(P2)
EXP_WAKEUP: J5.18 R207.1(P1)
EXP_XDMA_EVENT_INTR0: J5.28 R221.1(P1)
EXP_XDMA_EVENT_INTR1: J5.32 R228.1(P1)
GPMC_A0: J6.2 R193.1(P1)
GPMC_A1: J6.4 R196.1(P1)
GPMC_A2: J6.6 R198.1(P1)
GPMC_A3: J6.8 R202.1(P1)
GPMC_A4: J6.10 R206.1(P1)
GPMC_A5: J6.12 R209.1(P1)
GPMC_A6: J6.16 R214.1(P1)
GPMC_A7: J6.18 R217.1(P1)
GPMC_A8: J6.22 R223.1(P1)
GPMC_A9: J6.24 R226.1(P1)
GPMC_A10: J6.26 R230.1(P1)
GPMC_A11: J6.28 R233.1(P1)
JTAG_EMU0: J2.13(EMU0) R71.1(P1) U2.C14(EMU0///////GPIO3_7)
JTAG_EMU1: J2.14(EMU1) R70.1(P1) U2.B14(EMU1///////GPIO3_8)
JTAG_TCK: R74.2(P2) R75.2(P2) U2.A12(TCK)
JTAG_TDI: J2.3(TDI) U2.B11(TDI)
JTAG_TDO: J2.7(TDO) U2.A11(TDO)
JTAG_TMS: J2.1(TMS) U2.C11(TMS)
JTAG_TRSTN: J2.2(TRSTN) R79.2(P2) U2.B10(TRSTN)
LCD_DATA0: J7.4 R240.1(P1)
LCD_DATA1: J7.3 R241.1(P1)
LCD_DATA2: J7.6 R245.1(P1)
LCD_DATA3: J7.5 R246.1(P1)
LCD_DATA4: J7.8 R251.1(P1)
LCD_DATA5: J7.7 R252.1(P1)
LCD_DATA6: J8.15 R270.1(P1)
LCD_DATA7: J8.9 R259.1(P1)
LCD_DATA8: J8.11 R262.1(P1)
LCD_DATA9: J8.13 R266.1(P1)
LCD_DATA10: J7.10 R256.1(P1)
LCD_DATA11: J7.16 R267.1(P1)
LCD_DATA12: J7.9 R257.1(P1)
LCD_DATA13: J8.10 R258.1(P1)
LCD_DATA14: J7.12 R260.1(P1)
LCD_DATA15: J8.7 R254.1(P1)
LCD_DATA16: J8.8 R253.1(P1)
LCD_DATA17: J8.5 R248.1(P1)
LCD_DATA18: J8.6 R247.1(P1)
LCD_DATA19: J7.13 R264.1(P1)
LCD_DATA20: J8.3 R243.1(P1)
LCD_DATA21: J8.4 R242.1(P1)
LCD_DATA22: J7.14 R263.1(P1)
LCD_DATA23: J7.11 R261.1(P1)
LCD_DEN: J8.17 R273.1(P1)
LCD_HSYNC: J8.18 R272.1(P1)
LCD_I2C_SCL: J8.14 R265.1(P1)
LCD_I2C_SDA: J7.15 R268.1(P1)
LCD_PCLK: J8.16 R269.1(P1)
LCD_VSYNC: J7.17 R271.1(P1)
LCDA_PIN18: J7.18 R274.2(P2)
LDO_VRTC: C113.1 R557.2(P2) U5.5(OUT)
MCASP0_ACLKR: J6.17 R218.1(P1)
MCASP0_ACLKX: J6.1 R194.1
MCASP0_AHCLKR: J6.13 R211.2(P2)
MCASP0_AHCLKX: J6.27 R234.1(P1)
MCASP0_AXR0: J6.7 R203.2(P2)
MCASP0_AXR1: J6.23 R227.1(P1)
MCASP0_FSR: J6.21 R224.1(P1)
MCASP0_FSX: J6.5 R199.2(P2)
MMC_CD: J13.15(CD) R378.1(P1) R380.1(P1) U21.3(IO1)
MMC_CLK: J13.5(#5_MMC+/MMCM/RSMMC/MMC/SD) J13.20(#5_MINISD) R398.1(P1) U19.1(IO1)
MMC_CMD: J13.2(#2_MMC+/MMCM/RSMMC/MMC/SD) J13.17(#2_MINISD) R366.1(P1) R397.1(P1) U19.7(IO5)
MMC_D0: J13.7(#7_MMC+/MMCM/RSMMC/MMC/SD) J13.22(#7_MINISD) R367.1(P1) R399.1(P1) U19.2(IO2)
MMC_D1: J13.8(#8_MMC+/MMCM/SD) J13.23(#8_MINISD) R368.1(P1) R400.1(P1) U19.3(IO3)
MMC_D2: J13.9(#9_MMC+/MMCM/SD) J13.24(#9_MINISD) R369.1(P1) R401.1(P1) U19.6(IO4)
MMC_D3: J13.1(#1_MMC+/MMCM/RSMMC/MMC/SD) J13.16(#1_MINISD) R365.1(P1) R396.1(P1) U19.8(IO6)
MMC_D4: J13.10(#10_MMC+/MMCM) R370.1(P1) U20.1(IO1)
MMC_D5: J13.11(#11_MMC+/MMCM) R371.1(P1) U20.2(IO2)
MMC_D6: J13.12(#12_MMC+/MMCM) R372.1(P1) U20.7(IO5)
MMC_D7: J13.13(#13_MMC+/MMCM) R373.1(P1) U20.8(IO6)
MMC_WP: J13.14(SD_WP) R379.1(P1) U21.5(IO2)
NAND_ADVN_ALE: R137.1(P1) U9.17(ALE)
NAND_BE0N_CLE: R136.1(P1) U9.16(CLE)
NAND_CSN: R132.1(P1) R135.1(P1) U9.9(\\C\E\)
NAND_D0: R140.1(P1) U9.29(I/O0)
NAND_D1: R141.1(P1) U9.30(I/O1)
NAND_D2: R142.1(P1) U9.31(I/O2)
NAND_D3: R143.1(P1) U9.32(I/O3)
NAND_D4: R144.1(P1) U9.41(I/O4)
NAND_D5: R145.1(P1) U9.42(I/O5)
NAND_D6: R146.1(P1) U9.43(I/O6)
NAND_D7: R147.1(P1) U9.44(I/O7)
NAND_D8: R148.1(P1) U9.26(NC_IO8)
NAND_D9: R149.1(P1) U9.27(NC_IO9)
NAND_D10: R150.1(P1) U9.28(NC_IO10)
NAND_D11: R151.1(P1) U9.33(NC_IO11)
NAND_D12: R152.1(P1) U9.40(NC_IO12)
NAND_D13: R153.1(P1) U9.45(NC_IO13)
NAND_D14: R154.1(P1) U9.46(NC_IO14)
NAND_D15: R155.1(P1) U9.47(NC_IO15)
NAND_OEN: R134.1(P1) U9.8(\\R\E)
NAND_WAIT: R131.1(P1) R133.1(P1) U9.7(R/\B\)
NAND_WEN: R138.1(P1) U9.18(\\W\E)
NAND_WPN: R130.1(P1) R139.1(P1) U9.19(\\W\P)
PB_INTERRUPT: C118.1 R113.2(P2) R156.1(P1) R560.1(P1)
PM_ALERT: J17.4 R455.1(P1) U27.3(ALERT) U32.3(ALERT)
PM_VDDAADCN: J27.2 R501.3(SENS1)
PM_VDDAADCP: J27.1 R501.4(SENS2)
PM_VDDCOREN: R32.4(SENS2) U27.9(VIN-)
PM_VDDCOREP: R32.3(SENS1) U27.10(VIN+)
PM_VDDMPUN: R46.4(SENS2) U32.9(VIN-)
PM_VDDMPUP: R46.3(SENS1) U32.10(VIN+)
PM_VDDSDDRN: J20.2 R508.4(SENS2)
PM_VDDSDDRP: J20.1 R508.3(SENS1)
PM_VDDSHV1N: J26.2 R493.3(SENS1)
PM_VDDSHV1P: J26.1 R493.4(SENS2)
PM_VDDSHV2N: J38.2 R545.3(SENS1)
PM_VDDSHV2P: J38.1 R545.4(SENS2)
PM_VDDSHV3N: J39.2 R546.3(SENS1)
PM_VDDSHV3P: J39.1 R546.4(SENS2)
PM_VDDSHV4N: J30.2 R494.3(SENS1)
PM_VDDSHV4P: J30.1 R494.4(SENS2)
PM_VDDSHV5N: J32.2 R495.3(SENS1)
PM_VDDSHV5P: J32.1 R495.4(SENS2)
PM_VDDSHV6N: J34.2 R496.3(SENS1)
PM_VDDSHV6P: J34.1 R496.4(SENS2)
PM_VDDSN: J21.2 R498.3(SENS1)
PM_VDDSOSCN: J29.2 R506.3(SENS1)
PM_VDDSOSCP: J29.1 R506.4(SENS2)
PM_VDDSP: J21.1 R498.4(SENS2)
PM_VDDSRTCN: J35.2 R505.3(SENS1)
PM_VDDSRTCP: J35.1 R505.4(SENS2)
PM_VPLLCRLCDN: J24.2 R503.3(SENS1)
PM_VPLLCRLCDP: J24.1 R503.4(SENS2)
PM_VPLLDDRN: J33.2 R507.4(SENS2)
PM_VPLLDDRP: J33.1 R507.3(SENS1)
PM_VPLLMPUN: J22.2 R497.4(SENS2)
PM_VPLLMPUP: J22.1 R497.3(SENS1)
PM_VSRAMCOREN: J23.2 R500.4(SENS2)
PM_VSRAMCOREP: J23.1 R500.3(SENS1)
PM_VSRAMMPUN: J25.2 R499.4(SENS2)
PM_VSRAMMPUP: J25.1 R499.3(SENS1)
PM_VUSB1_8VN: J28.2 R502.4(SENS2)
PM_VUSB1_8VP: J28.1 R502.3(SENS1)
PM_VUSB3_3VN: J31.2 R504.4(SENS2)
PM_VUSB3_3VP: J31.1 R504.3(SENS1)
PMIC_DELAYEDRTCPORZ: R3.1(P1) U1.6(2B)
PMIC_GPIO: C114.1 R3.2(P2) R54.1(P1) R57.2(P2) R69.1(P1)
PMIC_I2C_SCL: R55.1(P1) R551.1(P1) U4.9(SCL_SCK)
PMIC_I2C_SDA: R56.1(P1) R550.1(P1) U4.8(SDA_SDI)
PMIC_INTN: R61.1(P1) R66.1(P1) U4.45(INT1)
PMIC_PWR_EN: R178.1(P1) R556.2(P2) U2.C6(PMIC_POWER_EN)
PMIC_PWRHOLD: R556.1(P1) U4.1(PWRHOLD)
PMIC_RESETOUTN: R1.2(P2) R65.2(P2) U4.40(NRESPWRON)
PMIC_SLEEP: R62.1(P1) U4.37(SLEEP)
PMICSR_I2C_SCL: R58.1(P1) U4.11(SCLSR_EN1)
PMICSR_I2C_SDA: R59.1(P1) U4.10(SDASR_EN2)
PORZ: R2.2(P2) R9.1(P1) U1.7(2Y)
PWR_SMPS1: L2.1 U4.35(SW1)
PWR_SMPS1_FB: R561.2(P2) R562.2(P2) U4.32(VFB1)
PWR_SMPS2: L3.1 U4.42(SW2)
PWR_SMPS3: L8.1 U4.31(SW3)
PWR_SWIO: L4.1 U4.14(SWIO)
PWR_VAUX1: C109.1 R474.1(P1) U4.46(VAUX1)
PWR_VAUX2: C110.1 R475.1(P1) U4.48(VAUX2)
PWR_VAUX33: C108.1 R463.2(P2) R466.1(P1) U4.4(VAUX33)
PWR_VDAC: C101.1 R471.1(P1) U4.22(VDAC)
PWR_VDD1_SMPS: C237.1 L2.2 R469.2(P2) R562.1(P1)
PWR_VDD2_SMPS: C239.1 L3.2 R468.2(P2) U4.44(VFB2)
PWR_VDD3_SMPS: L8.2 R470.2(P2) U4.30(VFB3)
PWR_VDDIO: R465.2(P2) R466.2(P2) U4.12(VDDIO)
PWR_VDIG1: C104.1 R464.2(P2) U4.7(VDIG1)
PWR_VDIG2: C103.1 R476.2(P2) U4.5(VDIG2)
PWR_VIO_SMPS: C241.1 L4.2 R465.1(P1) R467.2(P2) U4.16(VFBIO)
PWR_VMMC: C107.1 R477.2(P2) U4.2(VMMC)
PWR_VPLL: C102.1 R473.1(P1) U4.24(VPLL)
PWRMON_I2CSCL: J17.1 R453.1(P1) U27.5(SCL) U32.5(SCL)
PWRMON_I2CSDA: J17.2 R454.1(P1) U27.4(SDA) U32.4(SDA)
RS232_CTS: J12.8 U18.8(RIN2)
RS232_RTS: J12.7 U18.7(DOUT2)
RS232_RXD: J12.2 U18.13(RIN1)
RS232_TXD: J12.3 U18.14(DOUT1)
RTCK: J2.9(TCKRTN) R74.1(P1)
SDIO_GPMC_A1: R196.2(P2) R574.1(P1)
SDIO_GPMC_A2: R198.2(P2) R575.1(P1)
SDIO_GPMC_A3: R202.2(P2) R576.1(P1)
SDIO_GPMC_BE1N: R186.2(P2) R577.1(P1)
SDIO_GPMC_CLK: R181.2(P2) R572.1(P1)
SDIO_GPMC_CS3N: R187.2(P2) R573.1(P1)
SYS_RESETN: J3.26 R6.1(P1) R10.2(P2) R517.2(P2) U2.A10(WARMRSTN)
SYS_WARMRESETN: C117.1 J4.11 R10.1(P1) SW2.3 SW2.4
TCK: J2.11(TCK) R75.1(P1)
TSC_CLK: J9.5 R250.1(P1)
TSC_GIO0: J9.1 TP38.1
TSC_GIO1: J9.3 TP39.1
TSC_GIO2: J9.8 R255.1(P1)
TSC_I2CSCL: J9.4 R244.1(P1)
TSC_I2CSDA: J9.6 R249.1(P1)
TSC_RSV0: J9.7 TP40.1
TSC_RSV1_VREF: J9.9 TP41.1
UART0_CTSN: R364.1(P1) U18.9(ROUT2)
UART0_RTSN: R362.1(P1) U18.10(DIN2)
UART0_RXD: R363.1(P1) U18.12(ROUT1)
UART0_TXD: R361.1(P1) U18.11(DIN1)
USB0_CONN_DM: J14.2(DM) L5.3 U23.2(D-)
USB0_CONN_DP: J14.3(DP) L5.4 U23.1(D+)
USB0_DM: L5.2 U2.N18(USB0_DM)
USB0_DP: L5.1 U2.N17(USB0_DP)
USB0_ID: J14.4(ID) R381.2(P2) R571.1(P1) U2.P16(USB0_ID) U23.3(ID)
USB0_MEAS_IDN: Q5.G(GATE) R565.1(P1) R566.1(P1)
USB0_OVRCURN: R382.2(P2) R384.2(P2) U22.5(O\C\)
USB1_CONN_DM: J18.2(DM) L6.3 U30.2(D-)
USB1_CONN_DP: J18.3(DP) L6.4 U30.1(D+)
USB1_DM: L6.2 U2.R18(USB1_DM)
USB1_DP: L6.1 U2.R17(USB1_DP)
USB1_ID: R385.2(P2) U2.P17(USB1_ID) U30.3(ID)
USB1_OVRCURN: R410.2(P2) R412.2(P2) U29.5(O\C\)
USB5V_FB: R520.1(P1) R521.2(P2) U24.E3(FB)
VAUX1: J19.16 R474.2(P2) R502.1(I1)
VAUX2: FB2.2 FB6.2 FB8.2 FB20.2 J19.17 R68.2(P2) R475.2(P2)
VAUX33: J19.18 R463.1(P1) R504.1(I1)
VBCKUPBAT: BT1.1(POS) TP26.1 U4.27(VBACKUP)
VDAC: J19.14 R471.2(P2) R498.2(I2)
VDIG1: FB1.2 FB3.2 FB7.2 FB21.2 J19.11 R464.1(P1) R472.2(P2)
VDIG2: J19.12 R476.1(P1) R497.1(I1) R499.1(I1) R500.1(I1) R503.2(I2) R506.2(I2) R507.1(I1)
VMMC: FB4.2 FB5.2 J19.13 R477.1(P1)
VPLL: FB9.2 J19.15 R473.2(P2)
VPMIC_VRTC: C97.1 R53.1(P1) R60.2(P2) U4.29(VRTC)
VPP: U2.M5(VPP)
VPWRIN_FUSED: D2.1(CATHODE) F1.2 SW1.1
VPWRIN_JCK: D1.2(ANODE) J1.1
VPWRIN_PREFUSE: D1.1(CATHODE) F1.1
VREFP_ADC: C9.1 C10.1 C11.1 C12.1 R30.2(P2) U2.B9(VREFP)
VRTC: C1.1 C91.1 C111.1 J19.3 R53.2(P2) R54.2(P2) R505.2(I2) R557.1(P1) U1.5(2A) U1.8(VCC) U6.1(2A) U6.2(2B) U6.8(VCC)
VUSB_VBUS0: C183.1 C262.1 J14.1(VBUS) J36.1 R563.1 U22.6(OUT#6) U22.7(OUT#7) U22.8(OUT#8) U23.6(VBUS)
VUSB_VBUS1: C186.1 C265.1 J18.1(VBUS) J37.1 R558.1(P1) R564.1 U29.6(OUT#6) U29.7(OUT#7) U29.8(OUT#8) U30.6(VBUS)
N17759: C5.1 R7.1(P1) R8.2(P2) Y2.1
N120395: D3.2(ANODE) R50.1(P1)
N124510: J2.4(TDIS) R73.2(P2)
N150689: C3.2 R5.2(P2) Y1.1
N194366: C9.2 C10.2 C13.1 C14.1 R51.1(P1) U2.A9(VREFN)
N17034041: R114.2(P2) SW3.1
N17034069: R115.2(P2) SW3.2
N17034107: R116.2(P2) SW3.3
N17034117: R117.2(P2) SW3.4
N17034161: R118.2(P2) SW3.5
N17034171: R119.2(P2) SW3.6
N17034215: R120.2(P2) SW3.7
N17034225: R121.2(P2) SW3.8
N17107785: C98.1 U4.18(VREF)
N17298950: C179.1 U18.6(V-)
N17298952: C177.1 U18.2(V+)
N17298960: C176.2 U18.3(C1-)
N17298962: C178.1 U18.4(C2+)
N17298964: C178.2 U18.5(C2-)
N17298974: C176.1 U18.1(C1+)
N17345501: R122.2(P2) SW4.1
N17345515: R123.2(P2) SW4.2
N17345519: R124.2(P2) SW4.3
N17345529: R125.2(P2) SW4.4
N17345551: R126.2(P2) SW4.5
N17345553: R127.2(P2) SW4.6
N17345567: R128.2(P2) SW4.7
N17345577: R129.2(P2) SW4.8
N17563948: Q1.G(GATE) R84.1(P1) R85.1(P1) R86.2(P2) R509.1(P1)
N17563994: D4.2(ANODE) R80.1(P1)
N17563997: D4.1(CATHODE) Q1.D(DRAIN)
N17564510: D5.1(CATHODE) Q2.D(DRAIN)
N17564514: D5.2(ANODE) R81.1(P1)
N17564644: D6.1(CATHODE) Q3.D(DRAIN)
N17564648: D6.2(ANODE) R82.1(P1)
N17564780: D7.1(CATHODE) Q4.D(DRAIN)
N17564784: D7.2(ANODE) R83.1(P1)
N17564892: Q2.G(GATE) R87.1(P1) R88.1(P1) R93.2(P2) R510.1(P1)
N17564904: Q3.G(GATE) R89.1(P1) R90.1(P1) R95.2(P2) R511.1(P1)
N17564916: Q4.G(GATE) R91.1(P1) R92.1(P1) R94.2(P2) R512.1(P1)
N17574941: R1.1(P1) U1.1(2A)
N17684279: J8.12 R239.1(P1)
N17684406: R63.1(P1) U4.33(PWRON)
N17710761: R22.2(P2) U2.J3(DDR_VTP)
N17828529: TP2.1 U2.G2(DDR_RESETN)
N18136628: R72.1(P1) U7.7(WP)
N18365790: R57.1(P1) U4.39(GPIO_CKSYNC)
N18368859: R69.2(P2) U6.7(2Y)
N19440113: L9.1 U24.B1(L1#B1) U24.B2(L1#B2)
N19440133: L9.2 U24.D1(L2#D1) U24.D2(L2#D2)
N19440219: C264.1 U24.A3(VINA) U24.B3(VINA1) U24.C4(P\S\) U24.D4(VSEL)
N19490589: TP24.1 U2.A3(RESERVED)
N19558182: R544.1(P1) U32.2(A0)
N19577113: R64.1(P1) U4.26(BOOT0)
N19577116: R60.1(P1) U4.19(BOOT1)
N21001557: R112.2(P2) R156.2(P2) SW5.1 SW5.2
N21001559: R559.1(P1) R560.2(P2) SW5.3 SW5.4
N21339295: Q5.D(DRAIN) R23.2(P2)

Pads without a net: J2 6; J4 1 2 3 4 5 6 9 10 13 14 15 16 17 18 20 22 24 27; J12 1 4 6 9; J13 25 26; J17 5; R566 2; SW1 3; U2 D3; U4 20 21 25 38; U5 4; U6 3; U8 A2 L7; U9 1 2 3 4 5 6 10 11 14 15 20 21 22 23 24 35 38; U19 4 9; U20 3 4 6 9; U21 2; U23 5; U30 5; U31 A2 L7; Y1 2 3; Y2 2 4

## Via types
v1: diameter 0.508, hole 0.254, TOP to BOTTOM, 2141 vias
v2: diameter 0.457, hole 0.203, TOP to BOTTOM, 183 vias
v3: diameter 0.762, hole 0.457, TOP to BOTTOM, 9 vias

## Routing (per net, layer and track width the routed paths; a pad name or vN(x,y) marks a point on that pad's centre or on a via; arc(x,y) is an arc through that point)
DGND: length 749.9
  TOP w0.076: v1(95.56,59.04) U31.E7
  TOP w0.102: v1(76.75,79.16) 76.31,79.16 76.09,78.93 72.09,78.93 71.61,78.45 71.61,78.09 71.71,78 v1(71.71,77.13) 72.21,77.63 74.07,77.63 74.37,77.93 77.24,77.93 v2(77.51,78.2)
  TOP w0.121: v1(156.25,145.58) 156.39,145.73 U24.B4 ; v1(154.6,145.96) 154.89,146.25 U24.E4 ; U24.D3 U24.C3 U24.C2 U24.C1
  TOP w0.203: v3(88.18,33.69) 87.98,33.49 U4.43 ; U4.PPAD 88.05,34.64 U4.34 ; D9.2 v1(94.91,96.18) ; C111.2 87.43,23.02 87.67,22.78 U6.4 ; v1(89.89,100.57) 90.13,100.81 D10.2 ; U4.17 93.39,33.09 v1(93.51,33.22) ; v3(90.72,32.42) 90.85,32.29 U4.15
  TOP w0.254: U24.C1 v1(155.99,148.12) ; U19.5 v1(60.11,144.06) ; v1(60.24,99.1) 60.5,99.36 U1.4 ; U32.1 v1(61.86,36.72) ; U6.5 90.7,22.78 v1(90.46,23.02) 90.72,23.28 U6.6 ; U32.7 v1(65.77,34.65) ; v1(66.25,144.59) 65.73,144.06 U21.4
  TOP w0.305: v2(84.2,82.6) U2.J7 ; v1(154.98,117.51) 154.76,117.3 U9.25 ; v1(149.52,98.08) 149.25,97.82 U9.13 ; U9.48 v1(143.26,117.48) ; U2.A18 78.17,91.8 v2(78.09,91.88) ; U9.36 149.26,117.39 v1(149.52,117.64) ; v2(84.2,81.8) U2.J6 ; U2.A1 v2(77.51,78.2) ; v2(81.8,83.4) U2.F8 ; U2.V1 v2(92.5,78.2)
  TOP w0.381: FB14.1 v1(135.73,163.53) ; J14.5 v1(129.42,164.8) ; v1(98.76,62.24) U31.B2 ; v2(84.2,83.4) U2.J8 ; v1(149.07,162.91) 148.88,163.11 148.37,163.11 ; U2.H7 v2(84.2,82.6) ; C263.2 158.39,145.49 158.15,145.25 v1(158.15,144.44) ; U2.L12 v2(86.6,87.4) U2.L13 ; U2.M14 v2(87.4,89) U2.N14 ; U30.4 v1(149.07,161.89) 149.2,162.03 R385.1 ; U2.M9 v2(87.4,84.2) U2.M8 ; v1(74.94,57.44) U8.D8 ; v1(91.56,56.64) U31.K9 ; v1(133.9,163.84) 133.13,163.84 C183.2 133.01,163.68 133.07,163.62 133.07,163.15 132.87,162.95 U23.4 133.51,162.76 133.57,162.7 R381.1 ; U20.5 v1(71.92,151.29) ; v1(76.54,57.44) U8.B8 ; v2(84.2,85.8) U2.J10 ; v1(77.33,61.44) U8.A3 ; U2.H10 v2(83.4,85.8) U2.G11 ; v2(88.2,86.6) U2.N11 ; v1(99.56,61.44) U31.A3 ; C137.2 v1(141.64,88.05) ; 52.36,65.7 52.36,66.46 v1(52.11,66.71) ; v2(82.6,83.4) U2.G8 ; U5.2 v1(84.11,22.52) ; 29.41,87.92 v1(31.41,87.92) ; v1(92.36,63.84) U31.J1 ; C264.2 v1(155.61,142.91) ; v1(155.99,148.12) v1(155.99,148.88) v1(155.99,149.64) ; v2(87.4,81.8) U2.M6 ; v1(98.76,57.44) U31.B8 ; 97.07,87.79 v1(97.7,88.43) ; 29.41,85.38 v1(27.47,85.38) ; v2(87.4,82.6) U2.M7 ; v2(83.4,87.4) U2.H12 ; v2(85.8,82.6) U2.K7 ; J13.18 58.03,147.41 v1(58.33,147.1) 58.71,147.1 58.88,147.27 J13.6 ; v1(49.31,85) C28.2 ; v2(85.8,86.6) U2.K11 ; U2.H9 v2(83.4,84.2) U2.G9 ; J2.8 v1(31.28,93) ; J13.27 v1(67.4,163.92) ; v2(87.4,87.4) U2.M12 ; C187.2 159.68,145.33 v1(159.42,145.07) ; J13.28 v1(39.1,163.69) ; v1(97.16,62.24) U31.D2 ; R48.1 71.09,77.13 v1(71.71,77.13) ; v1(69.34,56.64) U8.K9 ; v2(86.6,86.6) U2.L11 ; v1(76.54,62.24) U8.B2 ; v2(85.8,85.8) U2.K10 ; U2.H6 v2(84.2,81.8) ; v1(99.69,58.64) U31.A7 ; v2(82.6,87.4) U2.G12 ; v1(97.16,57.44) U31.D8 ; v2(84.2,84.2) U2.J9 ; J2.10 v1(27.6,91.73) ; v2(88.2,85.8) U2.N10 ; v2(87.4,85.8) U2.M10 ; C175.2 v1(111.29,25.51) ; U2.J11 v2(84.2,86.6) ; C111.2 v1(87.03,22.26) ; v1(96.36,61.44) U31.E3 ; v2(88.2,82.6) U2.N7 ; v1(74.14,61.44) U8.E3 ; J2.12 v1(31.28,90.46) ; v2(86.6,85.8) U2.L10 ; v2(83.4,83.4) U2.H8 ; v1(77.33,58.24) U8.A7 ; v1(73.34,59.04) U8.E7 ; v1(74.94,62.24) U8.D2 ; v1(70.14,63.84) U8.J1 ; v2(85.8,84.2) U2.K9
  TOP w0.508: U2.V18 v2(91.8,92.37) ; Q1.S 7.4,88.24 v1(7.4,87.67) ; FB19.1 v1(156.18,163.55) ; C84.2 v1(96.31,13.75) ; C84.2 97.19,12.23 97.7,12.74 v1(97.7,13.75) ; C84.2 95.41,12.23 95.03,12.61 v1(95.03,13.88) ; C222.2 v1(69,33.44) ; D3.1 v1(83.62,15.93) ; C112.2 v1(86.02,23.28) ; v1(7.78,83.35) 7.78,83.54 Q2.S ; C128.2 v1(149.52,95.29) ; BT1.2 v1(106.32,43.82) ; SW2.2 v1(6.8,63.1) ; Q4.S 7.78,74.65 v1(7.78,74.46) ; R94.1 v1(12.36,75.22) ; C179.2 v1(103.16,16.67) ; 106.72,24.42 v1(105.88,24.42) ; C259.2 100.6,87.41 v1(101.76,87.41) ; C107.2 v1(87.03,25.82) ; U7.2 v1(139.67,63.73) ; C139.2 129.58,87.16 129.78,87.16 v1(129.82,87.2) ; R86.1 v1(12.23,88.56) ; J13.21 52.23,147.28 51.98,147.04 v1(51.85,147.04) 51.8,147.04 51.38,147.46 J13.3 ; C117.2 v1(12.28,60.36) ; v1(113.58,21.5) 113.32,21.75 U18.15 ; C234.2 92.75,17.71 v1(92.75,16.61) ; R95.1 v1(12.48,79.67) ; U7.3 v1(140.94,66.9) ; v1(78.4,22.9) 78.4,21.12 D2.2 79.16,20.48 79.92,21.25 v1(79.92,22.77) ; C131.2 v1(148.58,119.8) ; U7.4 v1(142.21,63.73) ; v1(7.78,78.78) 7.78,79.09 Q3.S ; C130.2 v1(150.86,119.8) ; C61.2 v1(118.35,136.94) ; 133.64,127.67 v1(133.64,126.94) ; C60.2 68.74,87.42 v1(68.5,87.67) ; C88.2 v1(92.63,19.34) ; R274.1 v1(141.77,75.98) ; 11.59,84.11 v1(12.15,83.58) ; C113.2 v1(82.21,21.25) ; U7.1 v1(138.4,66.84) ; C85.2 v1(92.6,20.36) ; SW2.1 v1(6.8,61.18) ; C86.2 v1(92.6,21.37) ; C103.2 v1(88.18,25.82) ; U22.1 v1(133.51,146.71) ; C114.2 v1(92.62,22.26) ; 110.53,136.82 v1(111.26,136.82) ; C133.2 v1(136.82,128.37) ; C255.2 v1(52.4,143.04) ; R2.1 v1(65.4,101.76)
  TOP w0.635: v1(62.65,69.38) 63.17,69.9 C232.2 ; U29.1 v1(140.8,144.83) ; 69.38,73.7 v1(70.4,73.7) ; C266.2 v1(70.76,71.01) ; C182.2 v1(124.37,150.47) ; C233.2 106.19,66.46 v1(106.72,66.46) ; v1(142.95,157.49) C265.2 v1(144.06,156.31) ; C185.2 v1(164.38,155.61)
  TOP w0.762: v1(137.51,156.25) C262.2 v1(138.62,157.68)
  LY2_GND w0.483: 138.01,75.09 J7.20 137.2,74.48 ; 135.93,74.48 J7.19 135.11,75.09 ; 133.56,75.09 J8.20 132.75,74.48 ; 130.67,75.09 J8.19 131.48,74.48
  LY2_GND w0.502: 124.73,116.75 J4.8 ; J4.8 125.64,115.84 ; J4.8 126.55,116.75 ; J4.8 125.64,117.66 ; SW1.M1 75.6,6.03 ; SW1.M1 76.52,5.12 ; SW1.M1 75.6,4.2 ; SW1.M1 74.69,5.12 ; 166.51,91.35 TP28.1 ; TP28.1 167.55,92.39 ; TP28.1 167.55,90.31 ; 57.06,124.73 J6.25 ; J6.25 57.97,125.64 ; J6.25 56.15,125.64 ; J6.25 57.06,126.55 ; 96.43,136.16 J5.1 ; J5.1 95.52,137.07 ; J5.1 97.34,137.07 ; J5.1 96.43,137.98 ; J5.10 87.18,139.61 ; J5.10 85.36,139.61 ; J5.10 86.27,138.7 ; J5.10 86.27,140.52 ; 7.12,93.51 TP27.1 ; TP27.1 8.17,94.55 ; TP27.1 9.21,93.51 ; TP27.1 8.17,92.47 ; J6.14 72.3,129.09 ; J6.14 73.21,128.18 ; J6.14 72.3,127.27 ; J6.14 71.39,128.18 ; 121.42,9.46 J12.5 ; J12.5 122.38,10.41 ; J12.5 121.42,11.37 ; J12.5 120.47,10.41 ; J19.5 123.74,53.21 ; J19.5 122.82,52.3 ; J19.5 123.74,51.38 ; J19.5 124.65,52.3 ; 84.09,125.64 J6.3 ; J6.3 85,126.55 ; J6.3 85.91,125.64 ; J6.3 85,124.73 ; J5.20 74.48,139.61 ; J5.20 73.57,140.52 ; J5.20 73.57,138.7 ; J5.20 72.66,139.61 ; 90.82,2.7 TP29.1 ; TP29.1 92.9,2.7 ; TP29.1 91.86,1.66 ; TP29.1 91.86,3.75 ; J19.10 123.74,40.51 ; J19.10 124.65,39.6 ; J19.10 123.74,38.68 ; J19.10 122.82,39.6 ; 83.73,136.16 J5.11 ; J5.11 82.82,137.07 ; J5.11 83.73,137.98 ; J5.11 84.64,137.07 ; J17.3 68.49,44.39 ; J17.3 68.49,42.3 ; J17.3 67.45,43.34 ; J17.3 69.53,43.34 ; TP30.1 86.04,167.55 ; TP30.1 83.96,167.55 ; TP30.1 85,166.51 ; J19.19 124.65,16.74 ; J19.19 122.82,16.74 ; J19.19 123.74,17.65 ; J19.19 123.74,15.82 ; 53.8,8.9 J1.3 ; J1.3 55.79,6.91 ; J1.3 55.79,10.9 ; J1.3 57.78,8.9 ; 59.96,139.61 J5.30 ; J5.30 60.87,140.52 ; J5.30 60.87,138.7 ; J5.30 61.78,139.61 ; 123.74,13.28 J19.20 ; J19.20 122.82,14.2 ; J19.20 124.65,14.2 ; J19.20 123.74,15.11 ; 128.18,115.84 J4.7 ; J4.7 128.18,117.66 ; J4.7 127.27,116.75 ; J4.7 129.09,116.75 ; SW1.M2 80.68,6.03 ; SW1.M2 79.77,5.12 ; SW1.M2 81.6,5.12 ; SW1.M2 80.68,4.2 ; 103.39,6.3 J12.11 ; J12.11 100.7,8.99 ; J12.11 106.08,8.99 ; J12.11 103.39,11.68 ; J12.10 128.38,11.68 ; J12.10 125.69,8.99 ; J12.10 131.08,8.99 ; J12.10 128.38,6.3 ; J3.27 136.71,91.35 ; J3.27 135.8,92.26 ; J3.27 134.89,91.35 ; J3.27 135.8,90.44 ; J5.37 51.62,137.07 ; J5.37 50.71,137.98 ; J5.37 49.8,137.07 ; J5.37 50.71,136.16 ; J3.28 134.17,91.35 ; J3.28 133.26,90.44 ; J3.28 133.26,92.26 ; J3.28 132.35,91.35 ; 141.46,165.01 J18.4 ; J18.4 142.45,166 ; J18.4 142.45,164.02 ; J18.4 143.44,165.01 ; 58.6,12.15 J1.2 ; J1.2 62.58,12.15 ; J1.2 60.59,10.16 ; J1.2 60.59,14.15 ; 64.68,127.27 J6.20 ; J6.20 64.68,129.09 ; J6.20 63.77,128.18 ; J6.20 65.59,128.18
  LY2_GND w0.635: 49.82,58.58 50.96,58.58
  LY4 w0.133: 88.04,44.33 88.04,39.76 87.92,39.64 87.92,38.52 v1(88.23,38.21) 88.51,38.21 88.94,38.65 88.94,44.61 81.85,51.7 81.85,59.21 83.35,60.71 83.35,65.6 80.66,68.29 80.11,68.29 73.8,74.61 73.8,77.38 72.27,78.9 71.77,78.9 71.51,78.65 71.51,77.32 v1(71.71,77.13) 72.55,77.13 72.93,76.75 72.93,74.39 80,67.32 80.55,67.32 82.52,65.35 82.52,60.96 81.06,59.51 81.06,59.5 80.97,59.4 80.97,51.41 88.04,44.33
  LY5_GND w0.483: 135.11,75.09 J7.19 135.93,74.48 ; 138.01,75.09 J7.20 137.2,74.48 ; 132.75,74.48 J8.20 133.56,75.09 ; 130.67,75.09 J8.19 131.48,74.48
  LY5_GND w0.502: 85,124.73 J6.3 ; J6.3 85.91,125.64 ; J6.3 84.09,125.64 ; J6.3 85,126.55 ; J5.1 96.43,137.98 ; J5.1 97.34,137.07 ; J5.1 95.52,137.07 ; J5.1 96.43,136.16 ; 122.82,39.6 J19.10 ; J19.10 123.74,38.68 ; J19.10 124.65,39.6 ; J19.10 123.74,40.51 ; TP27.1 8.17,94.55 ; TP27.1 7.12,93.51 ; TP27.1 9.21,93.51 ; TP27.1 8.17,92.47 ; J1.3 55.79,10.9 ; J1.3 57.78,8.9 ; J1.3 53.8,8.9 ; J1.3 55.79,6.91 ; 122.82,14.2 J19.20 ; J19.20 124.65,14.2 ; J19.20 123.74,13.28 ; J19.20 123.74,15.11 ; 121.42,9.46 J12.5 ; J12.5 120.47,10.41 ; J12.5 122.38,10.41 ; J12.5 121.42,11.37 ; 125.69,8.99 J12.10 ; J12.10 128.38,11.68 ; J12.10 128.38,6.3 ; J12.10 131.08,8.99 ; J5.37 50.71,137.98 ; J5.37 50.71,136.16 ; J5.37 51.62,137.07 ; J5.37 49.8,137.07 ; J18.4 142.45,166 ; J18.4 141.46,165.01 ; J18.4 142.45,164.02 ; J18.4 143.44,165.01 ; TP29.1 92.9,2.7 ; TP29.1 91.86,1.66 ; TP29.1 91.86,3.75 ; TP29.1 90.82,2.7 ; J19.19 123.74,17.65 ; J19.19 124.65,16.74 ; J19.19 123.74,15.82 ; J19.19 122.82,16.74 ; J3.27 135.8,92.26 ; J3.27 134.89,91.35 ; J3.27 135.8,90.44 ; J3.27 136.71,91.35 ; J6.25 57.97,125.64 ; J6.25 56.15,125.64 ; J6.25 57.06,126.55 ; J6.25 57.06,124.73 ; SW1.M1 76.52,5.12 ; SW1.M1 74.69,5.12 ; SW1.M1 75.6,4.2 ; SW1.M1 75.6,6.03 ; 132.35,91.35 J3.28 ; J3.28 133.26,92.26 ; J3.28 133.26,90.44 ; J3.28 134.17,91.35 ; 80.68,4.2 SW1.M2 ; SW1.M2 79.77,5.12 ; SW1.M2 80.68,6.03 ; SW1.M2 81.6,5.12 ; 72.66,139.61 J5.20 ; J5.20 74.48,139.61 ; J5.20 73.57,140.52 ; J5.20 73.57,138.7 ; 167.55,90.31 TP28.1 ; TP28.1 167.55,92.39 ; TP28.1 166.51,91.35 ; J6.14 72.3,129.09 ; J6.14 73.21,128.18 ; J6.14 72.3,127.27 ; J6.14 71.39,128.18 ; 59.96,139.61 J5.30 ; J5.30 60.87,140.52 ; J5.30 61.78,139.61 ; J5.30 60.87,138.7 ; 123.74,51.38 J19.5 ; J19.5 123.74,53.21 ; J19.5 124.65,52.3 ; J19.5 122.82,52.3 ; 63.77,128.18 J6.20 ; J6.20 64.68,129.09 ; J6.20 65.59,128.18 ; J6.20 64.68,127.27 ; 86.27,138.7 J5.10 ; J5.10 87.18,139.61 ; J5.10 85.36,139.61 ; J5.10 86.27,140.52 ; J17.3 68.49,44.39 ; J17.3 69.53,43.34 ; J17.3 68.49,42.3 ; J17.3 67.45,43.34 ; J12.11 106.08,8.99 ; J12.11 103.39,6.3 ; J12.11 100.7,8.99 ; J12.11 103.39,11.68 ; J5.11 83.73,137.98 ; J5.11 83.73,136.16 ; J5.11 84.64,137.07 ; J5.11 82.82,137.07 ; TP30.1 86.04,167.55 ; TP30.1 83.96,167.55 ; TP30.1 85,166.51 ; 128.18,115.84 J4.7 ; J4.7 129.09,116.75 ; J4.7 127.27,116.75 ; J4.7 128.18,117.66 ; 58.6,12.15 J1.2 ; J1.2 60.59,10.16 ; J1.2 60.59,14.15 ; J1.2 62.58,12.15 ; J4.8 125.64,117.66 ; J4.8 125.64,115.84 ; J4.8 126.55,116.75 ; J4.8 124.73,116.75
  BOTTOM w0.254: C148.2 74.52,122.85 74.21,123.16 v1(74.19,123.16) ; v1(77.33,61.44) 76.62,60.72 C221.2
  BOTTOM w0.305: v1(95.54,79.41) 94.84,79.41 C29.2 ; U27.2 72.68,47.53 72.81,47.65 v1(72.81,47.66) ; v1(64.55,46.9) C215.2 65.57,46.77 65.66,46.77 65.9,46.53 U27.7 ; C125.2 v1(71.03,68.17) ; 49.82,58.58 50.08,58.58 50.71,59.22 v1(50.78,59.22) ; U27.1 v1(71.63,48.61)
  BOTTOM w0.381: v1(96.24,72.11) 95.99,71.86 C80.2 ; v1(73.57,87.71) 74.5,87.71 C71.2 ; C217.2 v1(75.41,64.68) ; C77.2 81.76,83.36 v2(81.8,83.4) 81.8,84.09 C53.2 ; C155.2 v1(78.78,55.79) ; C41.2 82.6,86.7 v2(82.6,87.4) 81.89,88.11 C27.2 ; v1(74.3,86.33) 74.9,86.33 74.97,86.27 ; C42.2 83.41,87.41 v2(83.4,87.4) ; v2(84.2,90.6) 85,89.8 C83.2 ; C94.2 88.06,89 v2(87.4,89) ; C19.2 83.98,85.58 v2(84.2,85.8) ; v1(92.36,63.84) 91.86,64.34 C188.2 ; C31.2 87.4,83.3 v2(87.4,82.6) ; C218.2 69.63,65.12 v1(69.32,65.44) ; C195.2 99.24,59.2 99.24,59.08 v1(99.69,58.64) ; C189.2 v1(96.56,54.9) ; C24.2 84.76,82.6 v2(84.2,82.6) ; C78.2 87.25,81.95 v2(87.4,81.8) ; v1(99.56,61.44) 98.84,60.72 C156.2 ; v2(85.8,84.2) 85.55,84.2 85.13,84.62 C35.2 ; C82.2 98.03,72.11 v1(97.96,72.18) ; v1(72.55,63.98) 73.06,64.49 C219.2 ; v2(87.4,84.2) 87.03,84.57 C36.2 ; C64.2 106.46,66.2 v1(106.72,66.46) ; v1(93.51,33.22) 93.54,33.18 C98.2 ; v1(23.41,84.49) 24.17,85.25 C260.2 ; C181.2 v1(100.75,54.96) ; C266.2 v1(70.76,71.01) ; v2(83.4,83.4) 83.41,83.39 C76.2 ; R541.1 v1(85,77.44) ; C126.2 v1(72.11,54.96) ; v2(84.2,81.8) 84.85,81.8 C79.2 ; C47.2 78.19,91.78 v2(78.09,91.88) ; v1(91.56,56.64) 92.11,56.08 C174.2 ; C184.2 148.12,148.22 v1(148.88,148.98) ; v1(69.34,56.64) 69.89,56.08 C220.2 ; 95.29,64.68 v1(94.4,64.68) ; C34.2 84.72,86.08 v2(84.2,86.6) ; R22.1 v1(83.1,73.95) ; C90.2 88.57,85.42 88.57,85.43 v2(88.2,85.8) ; 71.92,82.71 C30.2 ; C216.2 v1(98.46,65.44) ; C66.2 66.14,60.4 65.89,60.65 65.88,60.65 v1(65.8,60.74) ; C141.2 64.93,122.59 v1(65.32,122.97) ; C89.2 v1(101.76,113.7)
  BOTTOM w0.508: C235.2 v1(93.62,46.92) ; R383.2 v1(138.49,145.64) ; C236.2 81.3,26.93 v1(80.8,26.93) ; C251.2 95.03,37.97 95.03,38.14 v1(95.92,39.03) ; v1(78.02,31.79) 78.41,32.18 C239.2 ; C101.2 97.95,36.61 98.34,36.99 v1(99.99,36.99) ; v1(51.85,147.04) 51.85,147.23 C180.2 ; v1(157.19,66.59) R115.1 R114.1 ; C93.2 98.21,89.22 v1(98.22,89.22) ; v1(94.03,90) 93.47,89.45 C50.2 ; C261.2 v1(113.59,45.01) ; C241.2 v1(100.73,33.68) ; C118.2 v1(7.91,43.34) R112.1 ; C116.2 138.91,67.35 v1(138.4,66.84) ; 82.59,34.33 82.59,30.9 C109.2 82.21,30.26 v1(80.68,30.26) ; C73.2 63.92,66.27 v1(63.73,66.46) ; C102.2 v1(97.95,39.03) ; v2(81.13,92.6) 81.26,92.6 81.37,92.49 C96.2 ; v1(87.03,25.82) 87.67,26.45 C108.2 ; v1(63.98,98.78) 63.98,99.67 C1.2 ; v1(157.19,56.43) R119.1 R118.1 ; v1(81.75,39.89) 84.03,39.89 C238.2 ; v1(157.19,89.19) R123.1 R122.1 ; v1(82.21,95.03) 82.59,94.65 82.59,94.53 ; C46.2 86.65,87.45 v2(86.6,87.4) ; R116.1 R117.1 v1(157.19,61.51) ; C104.2 v1(89.45,25.82) ; FB10.2 72.36,82.14 71.92,82.59 ; C110.2 81.32,29.25 80.81,28.74 v1(80.68,28.74) ; C245.2 112.59,21.3 113.37,21.3 v1(113.58,21.5) ; R4.1 60.74,99.61 v1(60.24,99.1) ; R120.1 R121.1 v1(157.19,51.35) ; C138.2 130.85,87.67 130.83,87.65 130.26,87.65 v1(129.82,87.2) ; C91.2 v1(93.64,42.33) ; C45.2 89.13,98.08 v1(89.89,98.84) ; 71.92,82.59 71.92,82.71 ; 71.92,82.59 v1(71.92,82.58) ; C115.2 v1(25.95,94.27) ; v1(157.19,78.96) 157.12,79.03 R127.1 R126.1 ; R64.2 90.84,35.09 v3(90.72,34.96) ; v1(157.26,84.11) 155.99,84.11 R124.1 ; C68.2 v1(50.2,101.38) ; v1(90.97,42.07) 91.6,41.44 91.6,40.17 ; C135.2 v1(48.17,133.39) ; C258.2 103.29,78.79 103.29,78.02 v1(103.16,77.89) ; R387.2 v1(145.64,143.36) ; C69.2 v1(50.08,96.94) ; C127.2 v1(149.52,98.08) ; C134.2 v1(71.03,122.85) ; C136.2 v1(134.53,84.62) ; C237.2 v1(83.87,45.14) ; C32.2 v1(105.7,82.59) ; C48.2 91.67,92.23 v2(91.8,92.37) ; R128.1 R129.1 157.14,73.95 v1(157.19,73.9) ; 95.29,113.45 v1(95.29,112.69) ; C129.2 v1(149.52,117.64) ; C273.2 v1(105.56,94.51) ; R73.1 R79.1 v1(27.47,96.81) ; v1(93.26,81.38) 93.26,82.02
  BOTTOM w0.635: v1(69.13,80.94) 68.62,80.94 68.36,81.19 C52.2 ; C247.2 52.16,82.42 v1(52.16,81.95) ; C56.2 72.51,80.6 v1(73.7,80.6) 73.75,80.65 74.43,80.65 C65.2 ; C249.2 v1(100.16,106.92) ; v1(90.84,106.7) 90.91,106.64 90.91,105.62 C257.2 ; C16.2 v1(65.06,78.02) ; C23.2 v1(71.16,72.94) ; v1(65.06,82.84) 66.08,82.84 66.57,83.33 C246.2 ; v1(84.49,99.88) 84.44,99.83 C274.2
  BOTTOM w0.762: v3(90.72,32.42) 90.42,32.13 C252.2 ; v3(89.45,34.96) 88.98,35.43 C250.2 ; C240.2 90.99,33.42 v3(90.72,33.69) ; C254.2 87.96,32.64 v3(88.18,32.42) ; C253.2 88.09,34.87 v3(88.18,34.96)
  vias: v1(2.45,98.97) v1(2.45,96.43) v1(2.45,93.89) v1(2.45,91.35) v1(2.45,70.4) v1(2.45,67.86) v1(2.45,65.32) v1(2.45,59.6) v1(2.45,57.06) v1(2.45,54.52) v1(2.45,51.98) v1(2.45,49.44) v1(2.45,45.63) v1(2.45,43.09) v1(2.45,40.55) v1(2.45,27.22) v1(2.45,25.31) v1(2.45,23.41) v1(2.45,21.5) v1(2.45,19.6) v1(2.45,17.69) v1(2.45,15.79) v1(2.45,13.88) v1(2.45,11.98) v1(2.45,10.07) v1(2.45,8.17) v1(2.45,6.26) v1(2.45,4.36) v1(2.45,2.45) v1(3.09,109.38) v1(4.36,157.39) v1(4.36,154.85) v1(4.36,152.31) v1(4.36,149.77) v1(4.36,147.23) v1(4.36,141.52) v1(4.36,116.12) v1(4.36,115.23) v1(4.36,109.38) v1(4.61,132.24) v1(4.61,122.47) v1(4.99,98.97) v1(4.99,96.43) v1(4.99,93.89) v1(4.99,91.35) v1(4.99,70.4) v1(4.99,67.86) v1(4.99,65.32) v1(4.99,59.6) v1(4.99,57.06) v1(4.99,54.52) v1(4.99,51.98) v1(4.99,49.44) v1(4.99,27.22) v1(4.99,25.31) v1(4.99,23.41) v1(4.99,21.5) v1(4.99,19.6) v1(4.99,17.69) v1(4.99,15.79) v1(4.99,13.88) v1(4.99,11.98) v1(4.99,10.07) v1(4.99,8.17) v1(4.99,6.26) v1(4.99,4.36) v1(4.99,2.45) v1(6.26,157.39) v1(6.26,154.85) v1(6.26,152.31) v1(6.26,149.77) v1(6.26,147.23) v1(6.64,101.64) v1(7.53,70.4) v1(7.53,67.86) v1(7.53,27.22) v1(7.53,25.31) v1(7.53,23.41) v1(7.53,21.5) v1(7.53,19.6) v1(7.53,17.69) v1(7.53,15.79) v1(7.53,13.88) v1(7.53,11.98) v1(7.53,10.07) v1(7.53,8.17) v1(7.53,6.26) v1(7.53,4.36) v1(7.53,2.45) v1(7.66,128.05) v1(7.66,111.42) v1(8.17,157.39) v1(8.17,154.85) v1(8.17,152.31) v1(8.17,149.77) v1(8.17,147.23) v1(10.07,157.39) v1(10.07,154.85) v1(10.07,152.31) v1(10.07,149.77) v1(10.07,147.23) v1(10.07,70.4) v1(10.07,67.86) v1(10.07,27.22) v1(10.07,25.31) v1(10.07,23.41) v1(10.07,21.5) v1(10.07,19.6) v1(10.07,17.69) v1(10.07,15.79) v1(10.07,13.88) v1(10.07,11.98) v1(10.07,10.07) v1(10.07,8.17) v1(10.07,6.26) v1(10.07,4.36) v1(10.07,2.45) v1(10.32,101.64) v1(11.98,157.39) v1(11.98,154.85) v1(11.98,152.31) v1(11.98,149.77) v1(11.98,147.23) v1(11.98,67.86) v1(12.23,115.48) v1(12.23,112.56) v1(12.36,132.63) v1(12.36,124.37) v1(12.36,122.08) v1(12.36,120.81) v1(12.48,140.25) v1(12.48,138.98) v1(12.48,137.07) v1(12.61,58.33) v1(12.61,56.43) v1(12.61,54.52) v1(12.61,52.62) v1(12.61,11.34) v1(12.61,5.63) v1(13.88,157.39) v1(13.88,154.85) v1(13.88,152.31) v1(13.88,149.77) v1(13.88,147.23) v1(13.88,48.81) v1(13.88,46.27) v1(13.88,43.73) v1(13.88,39.28) v1(13.88,35.47) v1(13.88,33.57) v1(13.88,31.66) v1(13.88,29.76) v1(13.88,27.85) v1(13.88,25.95) v1(13.88,24.04) v1(13.88,22.14) v1(13.88,20.23) v1(13.88,18.33) v1(13.88,15.79) v1(13.88,8.8) v1(13.88,2.45) v1(14.52,67.86) v1(14.64,101.51) v1(15.15,58.33) v1(15.15,56.43) v1(15.15,54.52) v1(15.15,52.62) v1(15.15,11.34) v1(15.15,5.63) v1(15.66,143.17) v1(15.79,157.39) v1(15.79,154.85) v1(15.79,152.31) v1(15.79,149.77) v1(15.79,147.23) v1(15.79,95.16) v1(15.79,92.62) v1(15.79,90.08) v1(15.79,87.54) v1(15.91,110.27) v1(16.42,39.28) v1(16.42,35.47) v1(16.42,33.57) v1(16.42,31.66) v1(16.42,29.76) v1(16.42,27.85) v1(16.42,25.95) v1(16.42,24.04) v1(16.42,22.14) v1(16.42,20.23) v1(16.42,18.33) v1(16.42,15.79) v1(16.42,8.8) v1(16.42,2.45) v1(17.06,83.73) v1(17.06,81.19) v1(17.06,78.65) v1(17.06,76.11) v1(17.06,72.94) v1(17.06,70.4) v1(17.06,67.86) v1(17.69,157.39) v1(17.69,154.85) v1(17.69,152.31) v1(17.69,149.77) v1(17.69,147.23) v1(17.69,11.34) v1(17.69,5.63) v1(18.2,104.05) v1(18.33,97.7) v1(18.33,95.16) v1(18.33,92.62) v1(18.33,90.08) v1(18.33,87.54) v1(18.69,101.02) v1(18.96,167.55) v1(18.96,165.65) v1(18.96,163.74) v1(18.96,39.28) v1(18.96,35.47) v1(18.96,33.57) v1(18.96,31.66) v1(18.96,29.76) v1(18.96,27.85) v1(18.96,25.95) v1(18.96,24.04) v1(18.96,22.14) v1(18.96,20.23) v1(18.96,18.33) v1(18.96,15.79) v1(18.96,8.8) v1(18.96,2.45) v1(19.6,157.39) v1(19.6,154.85) v1(19.6,152.31) v1(19.6,149.77) v1(19.6,147.23) v1(19.6,83.73) v1(19.6,81.19) v1(19.6,78.65) v1(19.6,76.11) v1(19.6,72.94) v1(19.6,70.4) v1(19.6,67.86) v1(19.6,51.35) v1(19.6,48.81) v1(19.6,46.27) v1(20.24,107.87) v1(20.23,11.34) v1(20.23,5.63) v1(20.87,167.55) v1(20.87,165.65) v1(20.87,163.74) v1(20.87,113.58) v1(20.87,97.7) v1(21.12,57.31) v1(21.12,54.77) v1(21.12,10.32) v1(21.5,157.39) v1(21.5,154.85) v1(21.5,152.31) v1(21.5,149.77) v1(21.5,147.23) v1(21.5,39.28) v1(21.5,35.47) v1(21.5,33.57) v1(21.5,31.66) v1(21.5,29.76) v1(21.5,27.85) v1(21.5,25.95) v1(21.5,24.04) v1(21.5,22.14) v1(21.5,20.23) v1(21.5,18.33) v1(21.5,15.79) v1(21.5,8.8) v1(21.5,2.45) v1(21.88,139.99) v1(21.88,136.18) v1(21.88,133.64) v1(21.88,129.83) v1(21.88,127.29) v1(21.88,123.48) v1(21.88,120.94) v1(21.88,117.13) v1(22.14,109.51) v1(22.14,108.62) v1(22.14,107.73) v1(22.14,51.35) v1(22.14,48.81) v1(22.14,46.27) v1(22.39,60.49) v1(22.77,167.55) v1(22.77,165.65) v1(22.77,163.74) v1(22.77,100.88) v1(23.02,109.51) v1(23.02,108.62) v1(23.02,107.73) v1(23.15,63.79) v1(23.91,111.54) v1(23.91,109.51) v1(23.91,108.62) v1(23.91,107.73) v1(24.04,158.03) v1(24.68,167.55) v1(24.68,165.65) v1(24.68,163.74) v1(24.68,139.99) v1(24.68,136.94) v1(24.68,133.64) v1(24.68,127.29) v1(24.68,120.94) v1(24.68,27.85) v1(24.68,25.31) v1(24.8,116.62) v1(25.13,105.65) v1(25.07,46.54) v1(25.31,100.88) v1(25.95,158.03) v1(26.58,167.55) v1(26.58,165.65) v1(26.58,163.74) v1(26.58,31.66) v1(27.22,27.85) v1(27.22,25.31) v1(27.22,20.23) v1(27.42,129.78) v1(27.47,123.61) v1(27.85,158.03) v1(27.85,151.04) v1(27.85,148.5) v1(27.85,107.35) v1(27.85,101.51) v1(28.49,167.55) v1(28.49,165.65) v1(28.49,163.74) v1(28.74,110.53) v1(29.76,158.03) v1(29.76,128.82) v1(29.76,126.91) v1(29.76,100.24) v1(29.76,38.01) v1(29.76,31.66) v1(29.76,20.23) v1(30.39,167.55) v1(30.39,165.65) v1(30.39,163.74) v1(30.39,151.04) v1(30.39,148.5) v1(30.39,101.51) v1(31.66,158.03) v1(31.66,38.01) v1(32.3,167.55) v1(32.3,165.65) v1(32.3,163.74) v1(32.3,128.82) v1(32.3,126.91) v1(32.3,100.24) v1(32.3,20.23) v1(33.57,158.03) v1(33.57,38.01) v1(34.2,167.55) v1(34.2,165.65) v1(34.2,163.74) v1(34.84,46.9) v1(34.84,45) v1(35.47,158.03) v1(35.47,151.68) v1(35.47,149.14) v1(35.47,146.6) v1(35.47,144.06) v1(35.47,141.52) v1(35.47,138.98) v1(35.47,137.07) v1(35.47,133.26) v1(35.47,131.36) v1(36.11,167.55) v1(36.11,165.65) v1(36.11,163.74) v1(36.11,39.28) v1(36.11,37.38) v1(36.11,35.47) v1(36.11,33.57) v1(36.11,31.66) v1(36.11,29.76) v1(36.11,27.85) v1(37.38,158.03) v1(37.5,46.65) v1(38.01,151.68) v1(38.01,149.14) v1(38.01,146.6) v1(38.01,144.06) v1(38.01,141.52) v1(38.01,138.98) v1(38.01,137.07) v1(38.01,133.26) v1(38.01,131.36) v1(38.65,39.28) v1(38.65,37.38) v1(38.65,35.47) v1(38.65,33.57) v1(38.65,31.66) v1(38.65,29.76) v1(38.65,27.85) v1(38.65,25.95) v1(38.65,24.04) v1(38.65,22.14) v1(39.03,46.77) v1(39.28,158.03) v1(40.55,144.06) v1(40.55,141.52) v1(40.55,138.98) v1(40.55,137.07) v1(40.55,133.26) v1(40.55,131.36) v1(41.19,158.03) v1(41.19,39.28) v1(41.19,37.38) v1(41.19,35.47) v1(41.19,33.57) v1(41.19,31.66) v1(41.19,29.76) v1(41.19,27.85) v1(41.19,25.95) v1(41.19,24.04) v1(41.19,22.14) v1(43.09,144.06) v1(43.09,141.52) v1(43.09,138.98) v1(43.09,137.07) v1(43.09,133.26) v1(43.09,131.36) v1(44.61,11.21) v1(45.63,46.9) v1(45.63,44.36) v1(46.27,144.06) v1(46.27,141.52) v1(46.27,32.3) v1(46.27,30.39) v1(46.27,28.49) v1(46.27,26.58) v1(46.27,24.68) v1(46.27,22.77) v1(46.27,20.87) v1(46.27,18.96) v1(46.27,17.06) v1(46.27,15.15) v1(46.9,12.61) v1(46.9,10.07) v1(46.9,6.9) v1(46.9,4.36) v1(48.17,32.3) v1(48.17,30.39) v1(48.17,28.49) v1(48.17,26.58) v1(48.17,24.68) v1(48.17,22.77) v1(48.17,20.87) v1(48.17,18.96) v1(48.17,17.06) v1(48.17,15.15) v1(48.81,144.06) v1(48.81,141.52) v1(51.98,72.3) v1(51.98,69.76) v1(53.89,39.92) v1(53.89,37.38) v1(53.89,33.57) v1(53.89,31.03) v1(58.33,78.65) v1(58.33,76.11) v1(60.87,29.76) v1(61.51,38.01) v1(63.41,29.76) v1(63.41,5.63) v1(63.41,3.72) v1(63.41,1.82) v1(64.05,38.01) v1(65.95,29.76) v1(65.95,5.63) v1(65.95,3.72) v1(65.95,1.82) v1(68.49,29.76) v1(68.49,5.63) v1(68.49,3.72) v1(68.49,1.82) v1(71.03,5.63) v1(71.03,3.72) v1(71.03,1.82) v1(71.67,28.49) v1(71.67,25.95) v1(73.57,165.01) v1(74.21,28.49) v1(74.21,25.95) v1(75.48,165.01) v1(75.48,156.12) v1(76.75,158.03) v1(76.75,15.79) v1(77.38,165.01) v1(78.02,156.12) v1(79.29,165.01) v1(79.29,158.03) v1(79.29,15.79) v1(81.19,165.01) v1(81.19,149.14) v1(83.1,165.01) v1(83.73,149.14) v1(85,165.01) v1(85,9.44) v1(86.27,5.63) v1(86.27,3.72) v1(86.91,165.01) v1(87.54,144.69) v1(87.54,9.44) v1(88.81,165.01) v1(88.81,5.63) v1(88.81,3.72) v1(90.08,144.69) v1(90.72,166.92) v1(90.72,165.01) v1(91.35,5.63) v1(92.62,166.92) v1(93.89,5.63) v1(94.53,166.92) v1(96.43,166.92) v1(98.34,166.92) v1(98.34,20.87) v1(98.34,17.06) v1(98.34,15.15) v1(99.22,27.02) v1(100.24,166.92) v1(100.88,20.87) v1(100.88,17.06) v1(100.88,15.15) v1(102.15,166.92) v1(102.78,14.52) v1(104.05,166.92) v1(105.32,14.52) v1(105.96,166.92) v1(107.86,166.92) v1(107.86,155) v1(109.77,166.92) v1(110.4,102.78) v1(111.04,121.83) v1(111.04,119.93) v1(111.04,118.02) v1(111.04,116.12) v1(112.31,166.92) v1(112.94,102.78) v1(113.58,121.83) v1(113.58,119.93) v1(113.58,118.02) v1(113.58,116.12) v1(114.21,37.38) v1(114.85,166.92) v1(114.85,32.3) v1(115.48,121.83) v1(115.48,119.93) v1(115.48,118.02) v1(115.48,116.12) v1(115.48,107.86) v1(115.48,105.96) v1(115.48,104.05) v1(115.86,127.16) v1(116.12,163.11) v1(116.12,161.2) v1(116.12,159.3) v1(116.12,39.92) v1(116.12,15.79) v1(116.75,37.38) v1(117.39,166.92) v1(117.44,78.95) v1(117.39,32.3) v1(118.02,121.83) v1(118.02,119.93) v1(118.02,118.02) v1(118.02,116.12) v1(118.02,107.86) v1(118.02,105.96) v1(118.02,104.05) v1(118.66,163.11) v1(118.66,161.2) v1(118.66,159.3) v1(118.66,52.62) v1(118.66,50.08) v1(118.66,39.92) v1(118.66,15.79) v1(120.56,165.01) v1(121.2,15.79) v1(121.83,127.55) v1(122.47,157.39) v1(123.1,165.01) v1(123.1,149.14) v1(123.1,126.28) v1(124.37,127.55) v1(125.01,157.39) v1(125.64,149.14) v1(125.64,126.28) v1(126.28,65.95) v1(126.28,63.41) v1(127.55,18.96) v1(127.55,16.42) v1(127.55,13.88) v1(130.09,16.42) v1(130.09,13.88) v1(131.36,24.04) v1(131.36,22.14) v1(131.65,27.72) v1(132.63,20.23) v1(133.9,24.04) v1(133.9,22.14) v1(133.9,3.72) v1(133.9,1.82) v1(135.17,20.23) v1(135.17,8.8) v1(135.17,6.9) v1(136.11,15.35) v1(136.44,3.72) v1(136.44,1.82) v1(137.07,24.04) v1(137.71,139.61) v1(137.71,8.8) v1(137.71,6.9) v1(140.25,139.61) v1(141.52,10.45) v1(142.15,18.58) v1(142.09,15.35) v1(142.15,12.1) v1(144.21,6.97) v1(147.23,67.86) v1(147.23,65.32) v1(147.23,60.24) v1(147.23,57.7) v1(147.16,7.03) v1(148.12,143.55) v1(148.66,7.04) v1(149.01,143.55) v1(150.16,7.07) v1(150.28,143.55) v1(151.29,143.55) v1(151.5,14.15) v1(151.66,7.08) v1(152.56,143.29) v1(152.95,12.61) v1(153.58,48.81) v1(153.58,46.27) v1(153.58,43.73) v1(153.58,41.19) v1(153.58,32.93) v1(153.58,30.39) v1(153.58,27.85) v1(153.58,25.31) v1(154.6,145.22) v1(154.6,144.51) v1(154.6,143.78) v1(154.57,143.04) v1(154.85,11.34) v1(155.49,48.81) v1(155.49,46.27) v1(155.49,43.73) v1(155.49,41.19) v1(155.49,13.88) v1(156.12,34.84) v1(156.12,32.3) v1(156.12,29.76) v1(156.12,27.22) v1(156.25,144.18) v1(156.22,143.27) v1(157.39,48.81) v1(157.39,46.27) v1(157.39,43.73) v1(157.39,41.19) v1(157.39,13.88) v1(157.39,11.34) v1(157.39,8.8) v1(157.39,6.26) v1(158.03,32.3) v1(158.03,29.76) v1(158.03,27.22) v1(158.53,19.09) v1(158.66,119.93) v1(158.66,118.02) v1(158.66,116.12) v1(158.66,114.21) v1(158.66,112.31) v1(158.66,110.4) v1(158.66,108.5) v1(158.66,106.59) v1(158.66,104.69) v1(158.66,102.78) v1(158.66,3.09) v1(159.93,34.84) v1(159.93,32.3) v1(159.93,29.76) v1(159.93,27.22) v1(160.57,142.79) v1(160.57,140.88) v1(160.57,138.98) v1(160.57,137.07) v1(160.57,135.17) v1(160.57,133.26) v1(160.57,131.36) v1(160.57,129.45) v1(160.57,127.55) v1(160.57,125.64) v1(160.82,19.6) v1(161.2,3.09) v1(161.84,116.12) v1(161.84,114.21) v1(161.84,112.31) v1(161.84,110.4) v1(161.84,108.5) v1(161.84,106.59) v1(161.84,104.69) v1(161.84,102.78) v1(161.84,100.88) v1(161.84,98.97) v1(162.47,48.17) v1(162.47,46.27) v1(162.47,44.36) v1(162.47,42.46) v1(162.47,40.55) v1(162.47,38.65) v1(162.47,36.74) v1(162.47,34.84) v1(162.47,32.93) v1(162.47,31.03) v1(162.47,29.12) v1(162.47,26.58) v1(163.11,154.22) v1(163.11,152.31) v1(163.11,150.41) v1(163.11,148.5) v1(163.11,146.6) v1(163.11,144.69) v1(163.11,142.79) v1(163.11,140.88) v1(163.11,138.98) v1(163.11,137.07) v1(163.11,19.6) v1(163.74,3.09) v1(164.38,116.12) v1(164.38,114.21) v1(164.38,112.31) v1(164.38,110.4) v1(164.38,108.5) v1(164.38,106.59) v1(164.38,104.69) v1(164.38,102.78) v1(164.38,100.88) v1(164.38,98.97) v1(165.01,48.17) v1(165.01,46.27) v1(165.01,44.36) v1(165.01,42.46) v1(165.01,40.55) v1(165.01,38.65) v1(165.01,36.74) v1(165.01,34.84) v1(165.01,32.93) v1(165.01,31.03) v1(165.01,29.12) v1(165.01,26.58) v1(165.65,154.22) v1(165.65,152.31) v1(165.65,150.41) v1(165.65,148.5) v1(165.65,146.6) v1(165.65,144.69) v1(165.65,142.79) v1(165.65,140.88) v1(165.65,138.98) v1(165.65,137.07) v1(166.28,3.09) v1(167.55,48.17) v1(167.55,46.27) v1(167.55,44.36) v1(167.55,42.46) v1(167.55,40.55) v1(167.55,38.65) v1(167.55,36.74) v1(167.55,34.84) v1(167.55,32.93) v1(167.55,31.03) v1(167.55,29.12) v1(167.55,26.58) v1(167.55,24.04) v1(167.55,21.5) v1(168.19,154.22) v1(168.19,152.31) v1(168.19,150.41) v1(168.19,148.5) v1(168.19,146.6) v1(168.19,144.69) v1(168.19,142.79) v1(168.19,140.88) v1(168.19,138.98) v1(168.19,137.07) v1(168.19,135.17) v1(168.19,133.26) v1(168.19,131.36) v1(168.19,129.45) v1(168.19,127.55) v1(168.19,125.64) v1(168.19,123.74) v1(168.19,121.83) v1(168.19,119.93) v1(168.19,118.02) v1(168.19,116.12) v1(168.19,114.21) v1(168.19,112.31) v1(168.19,110.4) v1(168.19,108.5) v1(168.19,106.59) v1(168.19,104.69) v1(168.19,102.78) v1(168.19,100.88) v1(168.19,98.97) v3(89.45,33.69) v3(89.45,32.42)
